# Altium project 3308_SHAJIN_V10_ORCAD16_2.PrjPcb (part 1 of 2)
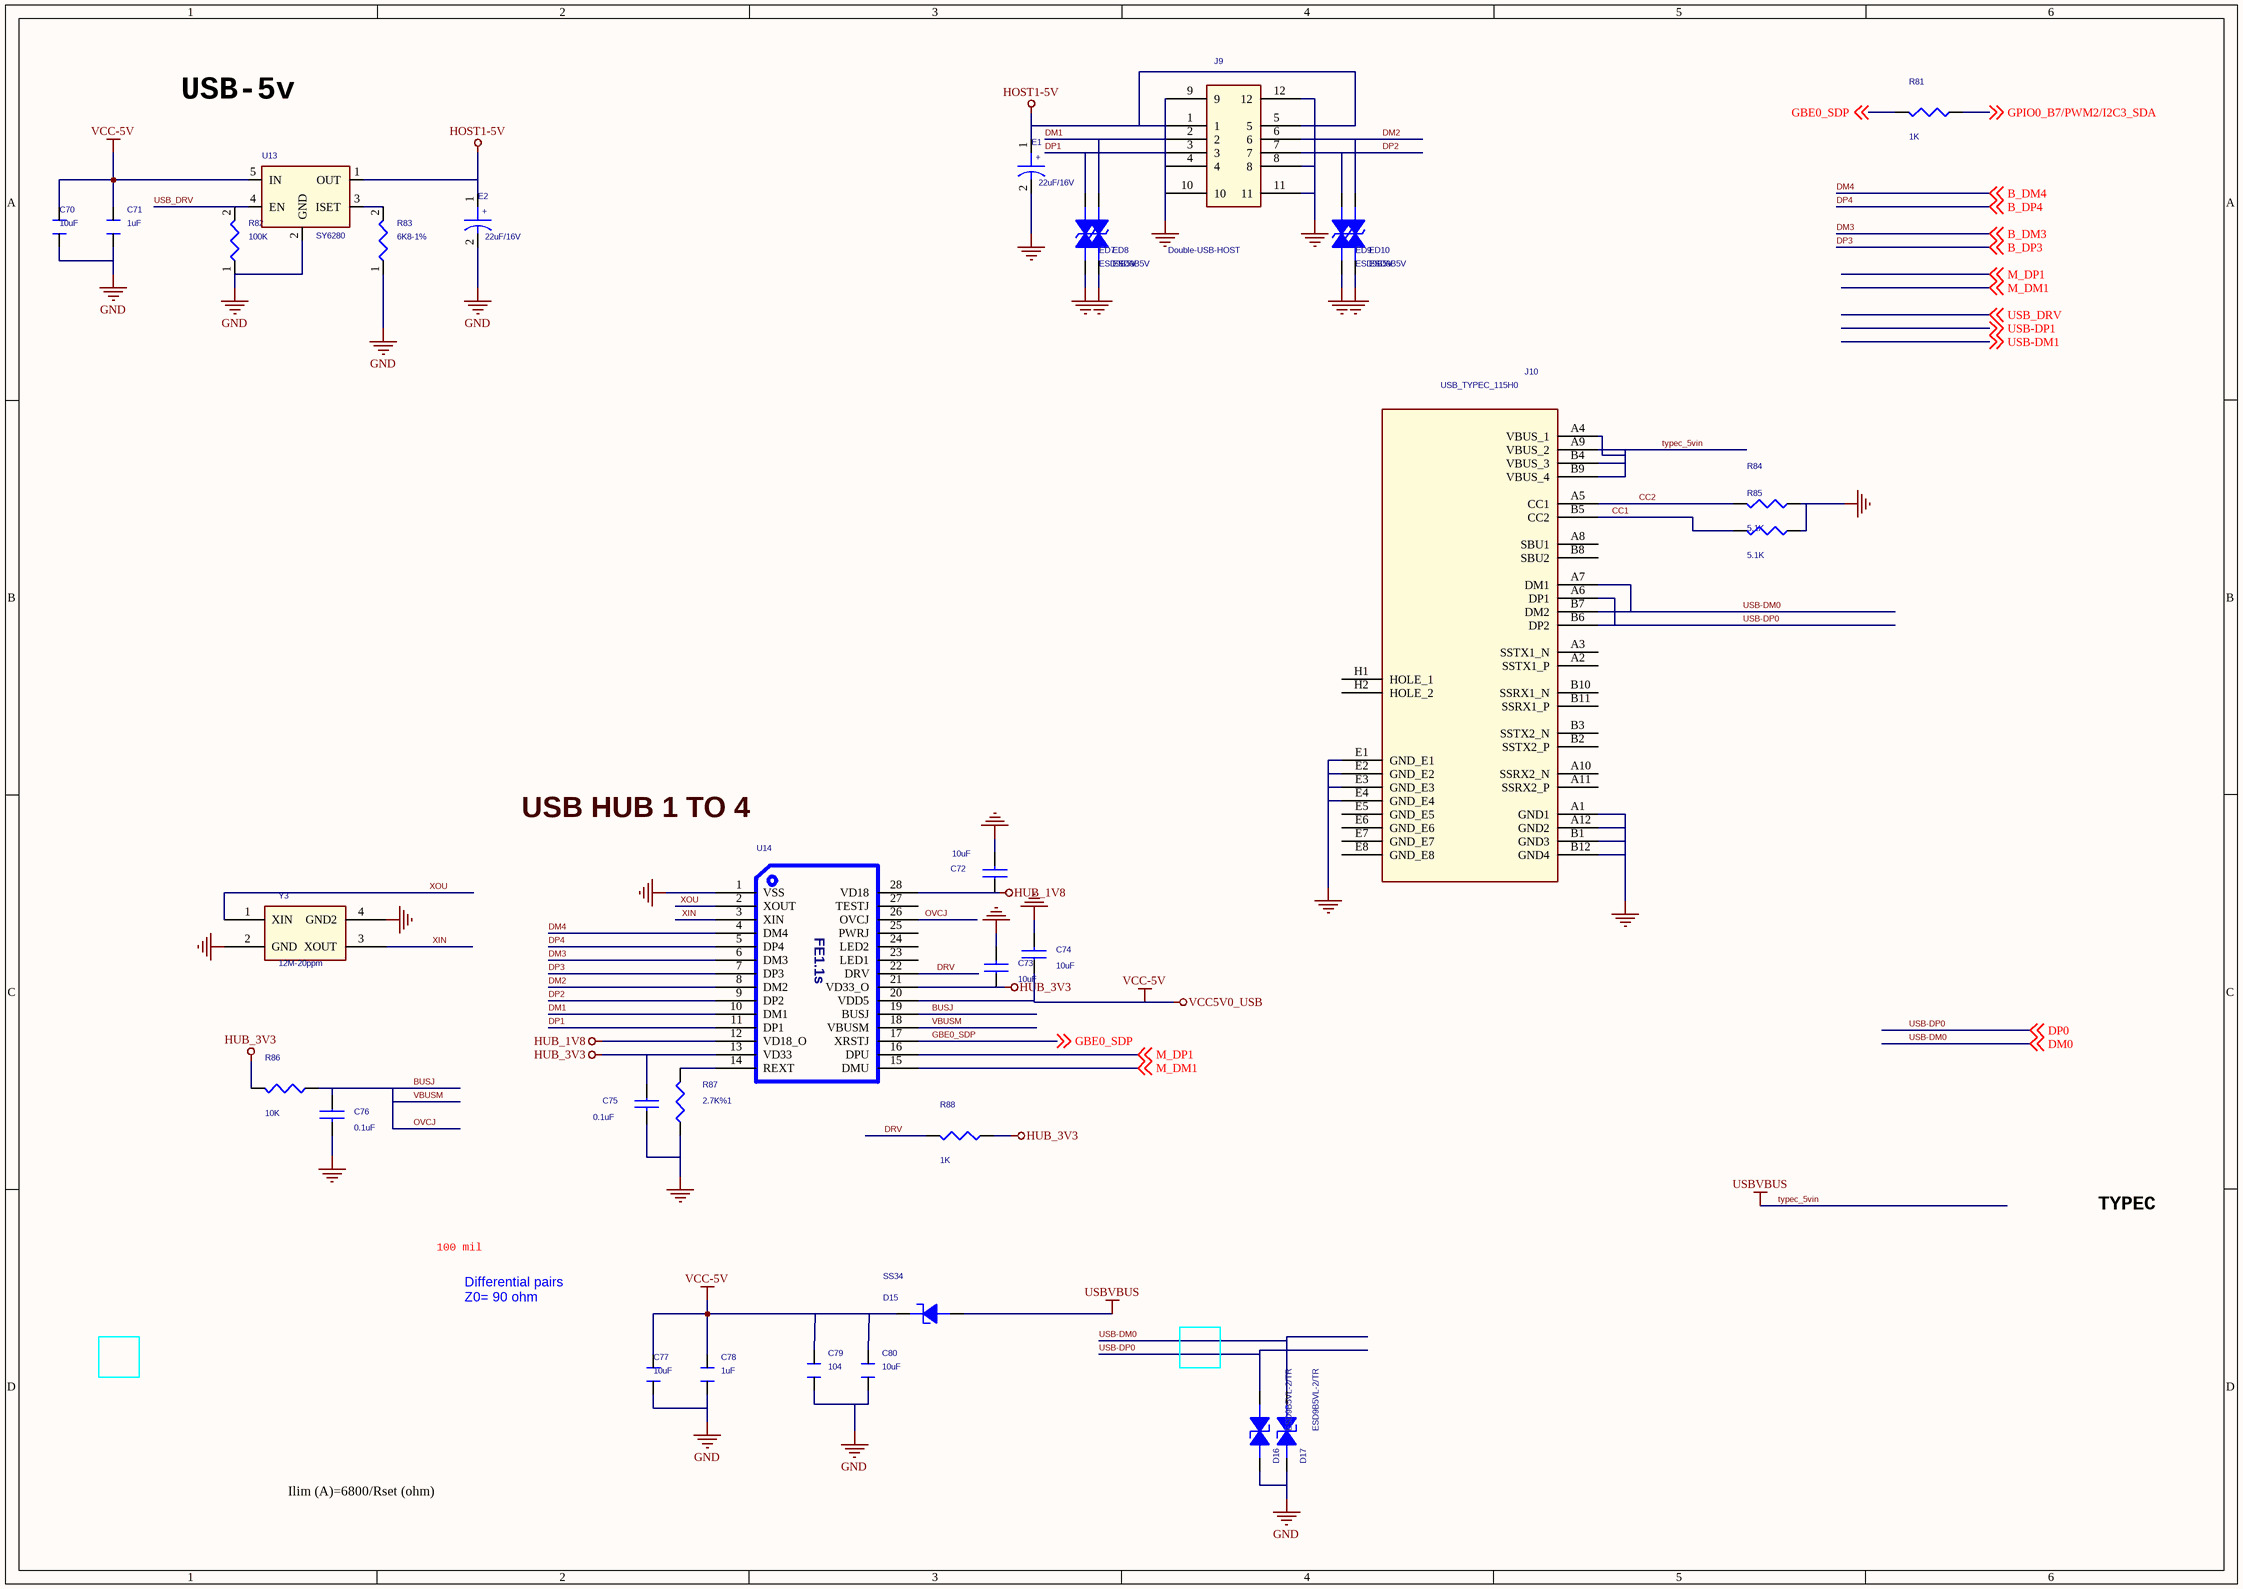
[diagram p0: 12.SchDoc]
11 sheets, 267 parts. Net scope: global (net labels, ports and power ports of the same name join across sheets).
Sheets:
  12.SchDoc
  11.SchDoc
  10.SchDoc
  09.SchDoc
  08.SchDoc
  07.SchDoc
  05.SchDoc
  04.SchDoc
  03.SchDoc
  02.SchDoc
  01.SchDoc

## Sheet 12.SchDoc
size 420 x 297 mm

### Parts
C70  10uF  [C0603]
C71  1uF  [C0402]
C72  10uF  [C0805]
C73  10uF  [C0805]
C74  10uF  [C0805]
C75  0.1uF  [C0402]
C76  0.1uF  [C0402]
C77  10uF  [C0603]
C78  1uF  [C0402]
C79  104  [C0402]
C80  10uF  [C0603]
D15  SS34  [SOD123]
D16  ESD9B5VL-2/TR  [C0402]
D17  ESD9B5VL-2/TR  [C0402]
E1  22uF/16V  [C0805]
E2  22uF/16V  [C0805]
ED7  ESD9B5V  [E0402]
ED8  ESD9B5V  [E0402]
ED9  ESD9B5V  [E0402]
ED10  ESD9B5V  [E0402]
J9  Double-USB-HOST  [USB_DUAL]
J10  USB_TYPEC_115H0  [TYPEC-16PIN-SMD1]
R81  1K  [R0402]
R82  100K  [R0402]
R83  6K8-1%  [R0402]
R84  5.1K  [R0402]
R85  5.1K  [R0402]
R86  10K  [R0402]
R87  2.7K%1  [R0402]
R88  1K  [R0402]
U13  SY6280  [SOT23-6]
U14  FE1_1s_SSOP28  [SSOP28-HUB]  (value not drawn)
Y3  12M-20ppm  [CRY-3225]

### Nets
GND: C70.1 C71.1 C72.2 C73.2 C74.2 C75.2 C76.2 C77.1 C78.1 C79.1 C80.1 D16.2(CATHODE) D17.2(CATHODE) E1.2 E2.2 ED7.2 ED8.2 ED9.2 ED10.2 J9.4 J9.8 J9.9 J9.10 J9.11 J9.12 J10.A1(GND1) J10.A12(GND2) J10.B1(GND3) J10.B12(GND4) J10.E1(GND_E1) J10.E2(GND_E2) J10.E3(GND_E3) J10.E4(GND_E4) R82.1 R83.1 R84.1 R85.1 R87.1 U13.2(GND) U14.1(VSS) Y3.2(GND) Y3.4(GND2)  [project net ABLU0]
HOST1-5V: E1.1 E2.1 J9.1 J9.5 U13.1(OUT)
HUB_1V8: C72.1 U14.12(VD18_O) U14.28(VD18)
HUB_3V3: C73.1 C75.1 R86.2 R88.1 U14.13(VD33) U14.21(VD33_O)
typec_5vin: D15.1(ANODE) J10.A4(VBUS_1) J10.A9(VBUS_2) J10.B4(VBUS_3) J10.B9(VBUS_4)  [also labelled USBVBUS]
VCC-5V: C70.2 C71.2 C74.1 C77.2 C78.2 C79.2 C80.2 D15.2(CATHODE) U13.5(IN) U14.20(VDD5)  [also labelled VCC5V0_USB]  [project net 5V]
B_DM3: U14.6(DM3) ; off-sheet B_DM3  [also labelled DM3]
B_DP3: U14.7(DP3) ; off-sheet B_DP3  [also labelled DP3]
BUSJ: C76.1 R86.1 U14.18(VBUSM) U14.19(BUSJ) U14.26(OVCJ)  [also labelled OVCJ, VBUSM]
CC1: J10.B5(CC2) R85.2
CC2: J10.A5(CC1) R84.2
DM1: ED8.1 J9.2 U14.10(DM1)
DM2: ED10.1 J9.6 U14.8(DM2)
DM4: U14.4(DM4) ; off-sheet B_DM4  [also labelled B_DM4]
DP1: ED7.1 J9.3 U14.11(DP1)
DP2: ED9.1 J9.7 U14.9(DP2)
DP4: U14.5(DP4) ; off-sheet B_DP4  [also labelled B_DP4]
DRV: R88.2 U14.22(DRV)
GBE0_SDP: R81.2 U14.17(XRSTJ) ; off-sheet GBE0_SDP
GPIO0_B7/PWM2/I2C3_SDA: R81.1 ; off-sheet GPIO0_B7/PWM2/I2C3_SDA
M_DM1: U14.15(DMU) ; off-sheet M_DM1
M_DP1: U14.16(DPU) ; off-sheet M_DP1
USB-DM0: D17.1(ANODE) J10.A7(DM1) J10.B7(DM2) ; off-sheet DM0  [also labelled DM0]
USB-DP0: D16.1(ANODE) J10.A6(DP1) J10.B6(DP2) ; off-sheet DP0  [also labelled DP0]
USB_DRV: R82.2 U13.4(EN) ; off-sheet USB_DRV
XIN: U14.3(XIN) Y3.3(XOUT)
XOU: U14.2(XOUT) Y3.1(XIN)
NetR83_2: R83.2 U13.3(ISET)
NetR87_2: R87.2 U14.14(REXT)

Not connected (* = marked no-connect by the designer): J10 A2(SSTX1_P) A3(SSTX1_N) A8(SBU1) A10(SSRX2_N) A11(SSRX2_P) B2(SSTX2_P) B3(SSTX2_N) B8(SBU2) B10(SSRX1_N) B11(SSRX1_P) E5(GND_E5) E6(GND_E6) E7(GND_E7) E8(GND_E8) H1(HOLE_1) H2(HOLE_2); U14 23(LED1) 24(LED2) 25(PWRJ) 27(TESTJ)

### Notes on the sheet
- USB-5v
- USB HUB 1 TO 4
- 100 mil
- Differential pairs
  Z0= 90 ohm
- TYPEC
- Ilim (A)=6800/Rset (ohm)

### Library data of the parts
C70 C71 C77-C80 = CAPACITOR: ROOM: HDMIUSB
C72-C74 = CAP NP: CAP,MLCC,10uF,+/-10%,X5R,6.3V,SMD0805
C75 C76 = CAP NP: CAP,MLCC,8pF,+/-0.5pF,NPO,6.3V,SMD0402
D15 = DIODE ZENER
D16 D17 = 1_1.5KE100A: 1ST PART DESCRIPTION: WILL ESD9B5V Bidirection ESD Protection; ROOM: HDMIUSB
E1 E2 = CAPACITOR POL_0
ED7-ED10 = DIODE_TVS: ESD Component,5V,0.5P,SMD,0402
J9 = CON4_1
J10 = USB31_TYPE_C: USB Type-C 连接座; Manufacturer: 泰科; Priority: A
R81 R86-R88 = RESISTOR
R82 R83 = R_1: ROOM: HDMIUSB
R84 R85 = R
U13 = RT9266PE_2: ROOM: HDMIUSB
Y3 = CRYSTAL-4_3: Crystal,24.000MHz,+/-30ppm,12pF,SMD3225,-10°C ~ +60   °C

## Sheet 11.SchDoc
size 297 x 209 mm
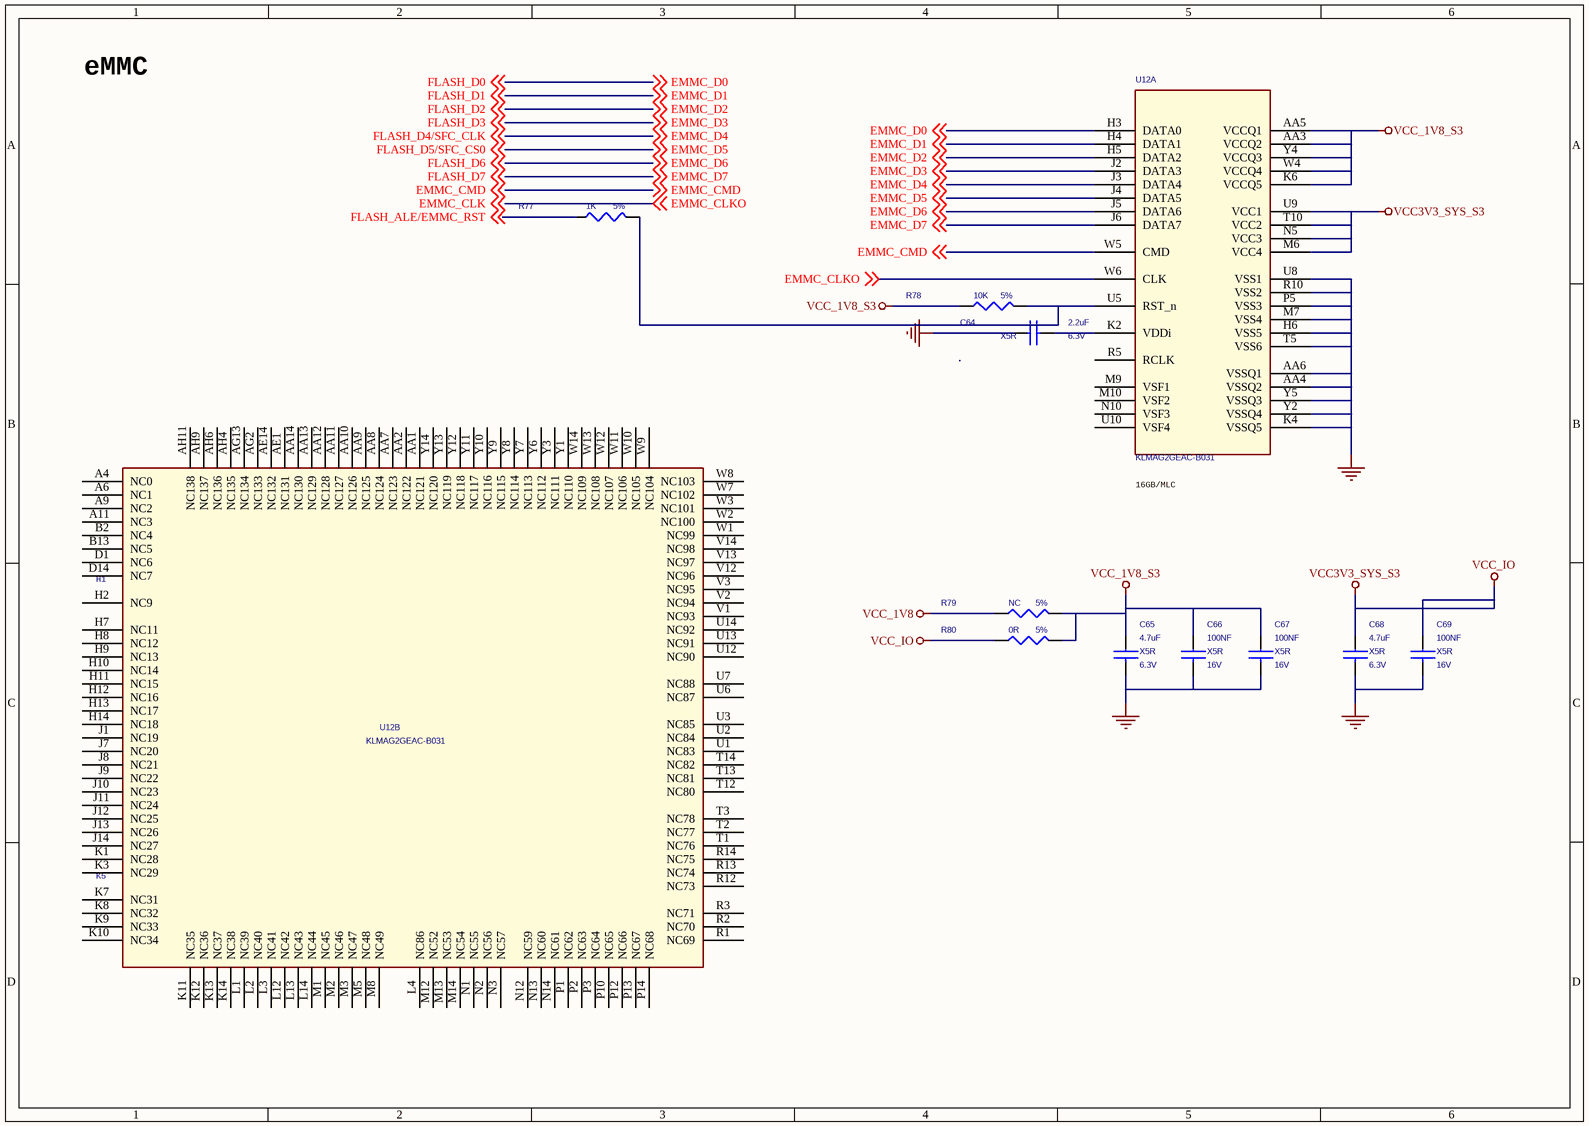
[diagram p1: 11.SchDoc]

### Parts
C64  2.2uF  Dielectric: X5R  Voltage: 6.3V  [C0402]
C65  4.7uF  Dielectric: X5R  Voltage: 6.3V  [C0402]
C66  100NF  Dielectric: X5R  Voltage: 16V  [C0201]
C67  100NF  Voltage: 16V  Dielectric: X5R  [C0201]
C68  4.7uF  Voltage: 6.3V  Dielectric: X5R  [C0402]
C69  100NF  Dielectric: X5R  Voltage: 16V  [C0201]
R77  1K  Tolerance: 5%  [R0402]
R78  10K  Tolerance: 5%  [R0402]
R79  NC  Tolerance: 5%  [R0402]
R80  0R  Tolerance: 5%  [R0402]
U12  KLMAG2GEAC-B031  [INAND_169]  (parts A,B of 2)

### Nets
GND: C64.1 C65.2 C66.2 C67.2 C68.2 C69.2 U12.AA4(VSSQ2) U12.AA6(VSSQ1) U12.H6(VSS5) U12.K4(VSSQ5) U12.M7(VSS4) U12.P5(VSS3) U12.R10(VSS2) U12.T5(VSS6) U12.U8(VSS1) U12.Y2(VSSQ4) U12.Y5(VSSQ3)  [project net ABLU0]
VCC3V3_SYS_S3: C68.1 C69.1 R80.1 U12.M6(VCC4) U12.N5(VCC3) U12.T10(VCC2) U12.U9(VCC1)  [also labelled VCC_IO]  [project net VCC3V3_SYS]
VCC_1V8: R79.1
VCC_1V8_S3: C65.1 C66.1 C67.1 R78.1 R79.2 R80.2 U12.AA3(VCCQ2) U12.AA5(VCCQ1) U12.K6(VCCQ5) U12.W4(VCCQ4) U12.Y4(VCCQ3)
EMMC_CLK: U12.W6(CLK) ; off-sheet EMMC_CLKO, off-sheet EMMC_CLK  [also labelled EMMC_CLKO]
EMMC_CMD: U12.W5(CMD) ; off-sheet EMMC_CMD
EMMC_D0: U12.H3(DATA0) ; off-sheet EMMC_D0, off-sheet FLASH_D0  [also labelled FLASH_D0]
EMMC_D1: U12.H4(DATA1) ; off-sheet EMMC_D1, off-sheet FLASH_D1  [also labelled FLASH_D1]
EMMC_D2: U12.H5(DATA2) ; off-sheet EMMC_D2, off-sheet FLASH_D2  [also labelled FLASH_D2]
EMMC_D3: U12.J2(DATA3) ; off-sheet EMMC_D3, off-sheet FLASH_D3  [also labelled FLASH_D3]
EMMC_D4: U12.J3(DATA4) ; off-sheet EMMC_D4, off-sheet FLASH_D4/SFC_CLK  [also labelled FLASH_D4/SFC_CLK]
EMMC_D5: U12.J4(DATA5) ; off-sheet EMMC_D5, off-sheet FLASH_D5/SFC_CS0  [also labelled FLASH_D5/SFC_CS0]
EMMC_D6: U12.J5(DATA6) ; off-sheet EMMC_D6, off-sheet FLASH_D6  [also labelled FLASH_D6]
EMMC_D7: U12.J6(DATA7) ; off-sheet EMMC_D7, off-sheet FLASH_D7  [also labelled FLASH_D7]
FLASH_ALE/EMMC_RST: R77.1 ; off-sheet FLASH_ALE/EMMC_RST
NetC64_2: C64.2 U12.K2(VDDi)
NetR77_2: R77.2 R78.2 U12.U5(RST_n)

Not connected (* = marked no-connect by the designer): U12 A4(NC0) A6(NC1) A9(NC2) A11(NC3) AA1(NC121) AA2(NC122) AA7(NC123) AA8(NC124) AA9(NC125) AA10(NC126) AA11(NC127) AA12(NC128) AA13(NC129) AA14(NC130) AE1(NC131) AE14(NC132) AG2(NC133) AG13(NC134) AH4(NC135) AH6(NC136) AH9(NC137) AH11(NC138) B2(NC4) B13(NC5) D1(NC6) D14(NC7) H2(NC9) H7(NC11) H8(NC12) H9(NC13) H10(NC14) H11(NC15) H12(NC16) H13(NC17) H14(NC18) J1(NC19) J7(NC20) J8(NC21) J9(NC22) J10(NC23) J11(NC24) J12(NC25) J13(NC26) J14(NC27) K1(NC28) K3(NC29) K7(NC31) K8(NC32) K9(NC33) K10(NC34) K11(NC35) K12(NC36) K13(NC37) K14(NC38) L1(NC39) L2(NC40) L3(NC41) L4(NC86) L12(NC42) L13(NC43) L14(NC44) M1(NC45) M2(NC46) M3(NC47) M5(NC48) M8(NC49) M9(VSF1) M10(VSF2) M12(NC52) M13(NC53) M14(NC54) N1(NC55) N2(NC56) N3(NC57) N10(VSF3) N12(NC59) N13(NC60) N14(NC61) P1(NC62) P2(NC63) P3(NC64) P10(NC65) P12(NC66) P13(NC67) P14(NC68) R1(NC69) R2(NC70) R3(NC71) R5(RCLK) R12(NC73) R13(NC74) R14(NC75) T1(NC76) T2(NC77) T3(NC78) T12(NC80) T13(NC81) T14(NC82) U1(NC83) U2(NC84) U3(NC85) U6(NC87) U7(NC88) U10(VSF4) U12(NC90) U13(NC91) U14(NC92) V1(NC93) V2(NC94) V3(NC95) V12(NC96) V13(NC97) V14(NC98) W1(NC99) W2(NC100) W3(NC101) W7(NC102) W8(NC103) W9(NC104) W10(NC105) W11(NC106) W12(NC107) W13(NC108) W14(NC109) Y1(NC110) Y3(NC111) Y6(NC112) Y7(NC113) Y8(NC114) Y9(NC115) Y10(NC116) Y11(NC117) Y12(NC118) Y13(NC119) Y14(NC120)

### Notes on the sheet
- eMMC
- 16GB/MLC

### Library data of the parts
C64 = CAP NP: cap,2.20uF,+/-10%,6.3V,X5R,C0402; Manufacturer: TDK; RK PN: C1005X5R0J225K050BC; Priority: A; Tolerance: 10%
C65 = CAP NP: cap,4.70uF,+/-10%,6.3V,X5R,C0402; Manufacturer: TDK; RK PN: C1005X5R0J475K050BC; Priority: A; Tolerance: 10%
C66 C69 = CAP NP: cap,100.00nF,+/-10%,16V,X5R,C0402; Manufacturer: TDK; RK PN: C1005X5R1C104K050BA; Priority: A; Tolerance: 10%
C67 = CAP NP: cap,100.00nF,+/-10%,16V,X5R,C0402; Manufacturer PN: C1005X5R1C104K050BA; Manufacturer: TDK; Tolerance: 10%; Priority: A
C68 = CAP NP: cap,4.70uF,+/-10%,6.3V,X5R,C0402; Manufacturer PN: C1005X5R0J475K050BC; Manufacturer: TDK; Tolerance: 10%; Priority: A
R77 R78 = RESISTOR: 通用厚膜电阻,10K,+/-5%,R0402,1/16W.; Manufacturer PN: RC0402JR-0710KL; Manufacturer: YAGEO; Wattage: 1/16W; Priority: A
R79 R80 = RESISTOR: 通用厚膜电阻,10K,+/-5%,R0402,1/16W.; Manufacturer: YAGEO; RK PN: RC0402JR-0710KL; Priority: A; Wattage: 1/16W
U12 = INAND_EMMC_169_2L: 64Gb MLCx2,16GB,EMMC5.0,19nm,5.0,11.5 x 13,更好的满足工艺需求，Fanout方式部分走线跨接再球位上，挖除H1\K5球位; Manufacturer: Samsung（三星）; Priority: A

## Sheet 10.SchDoc
size 420 x 297 mm
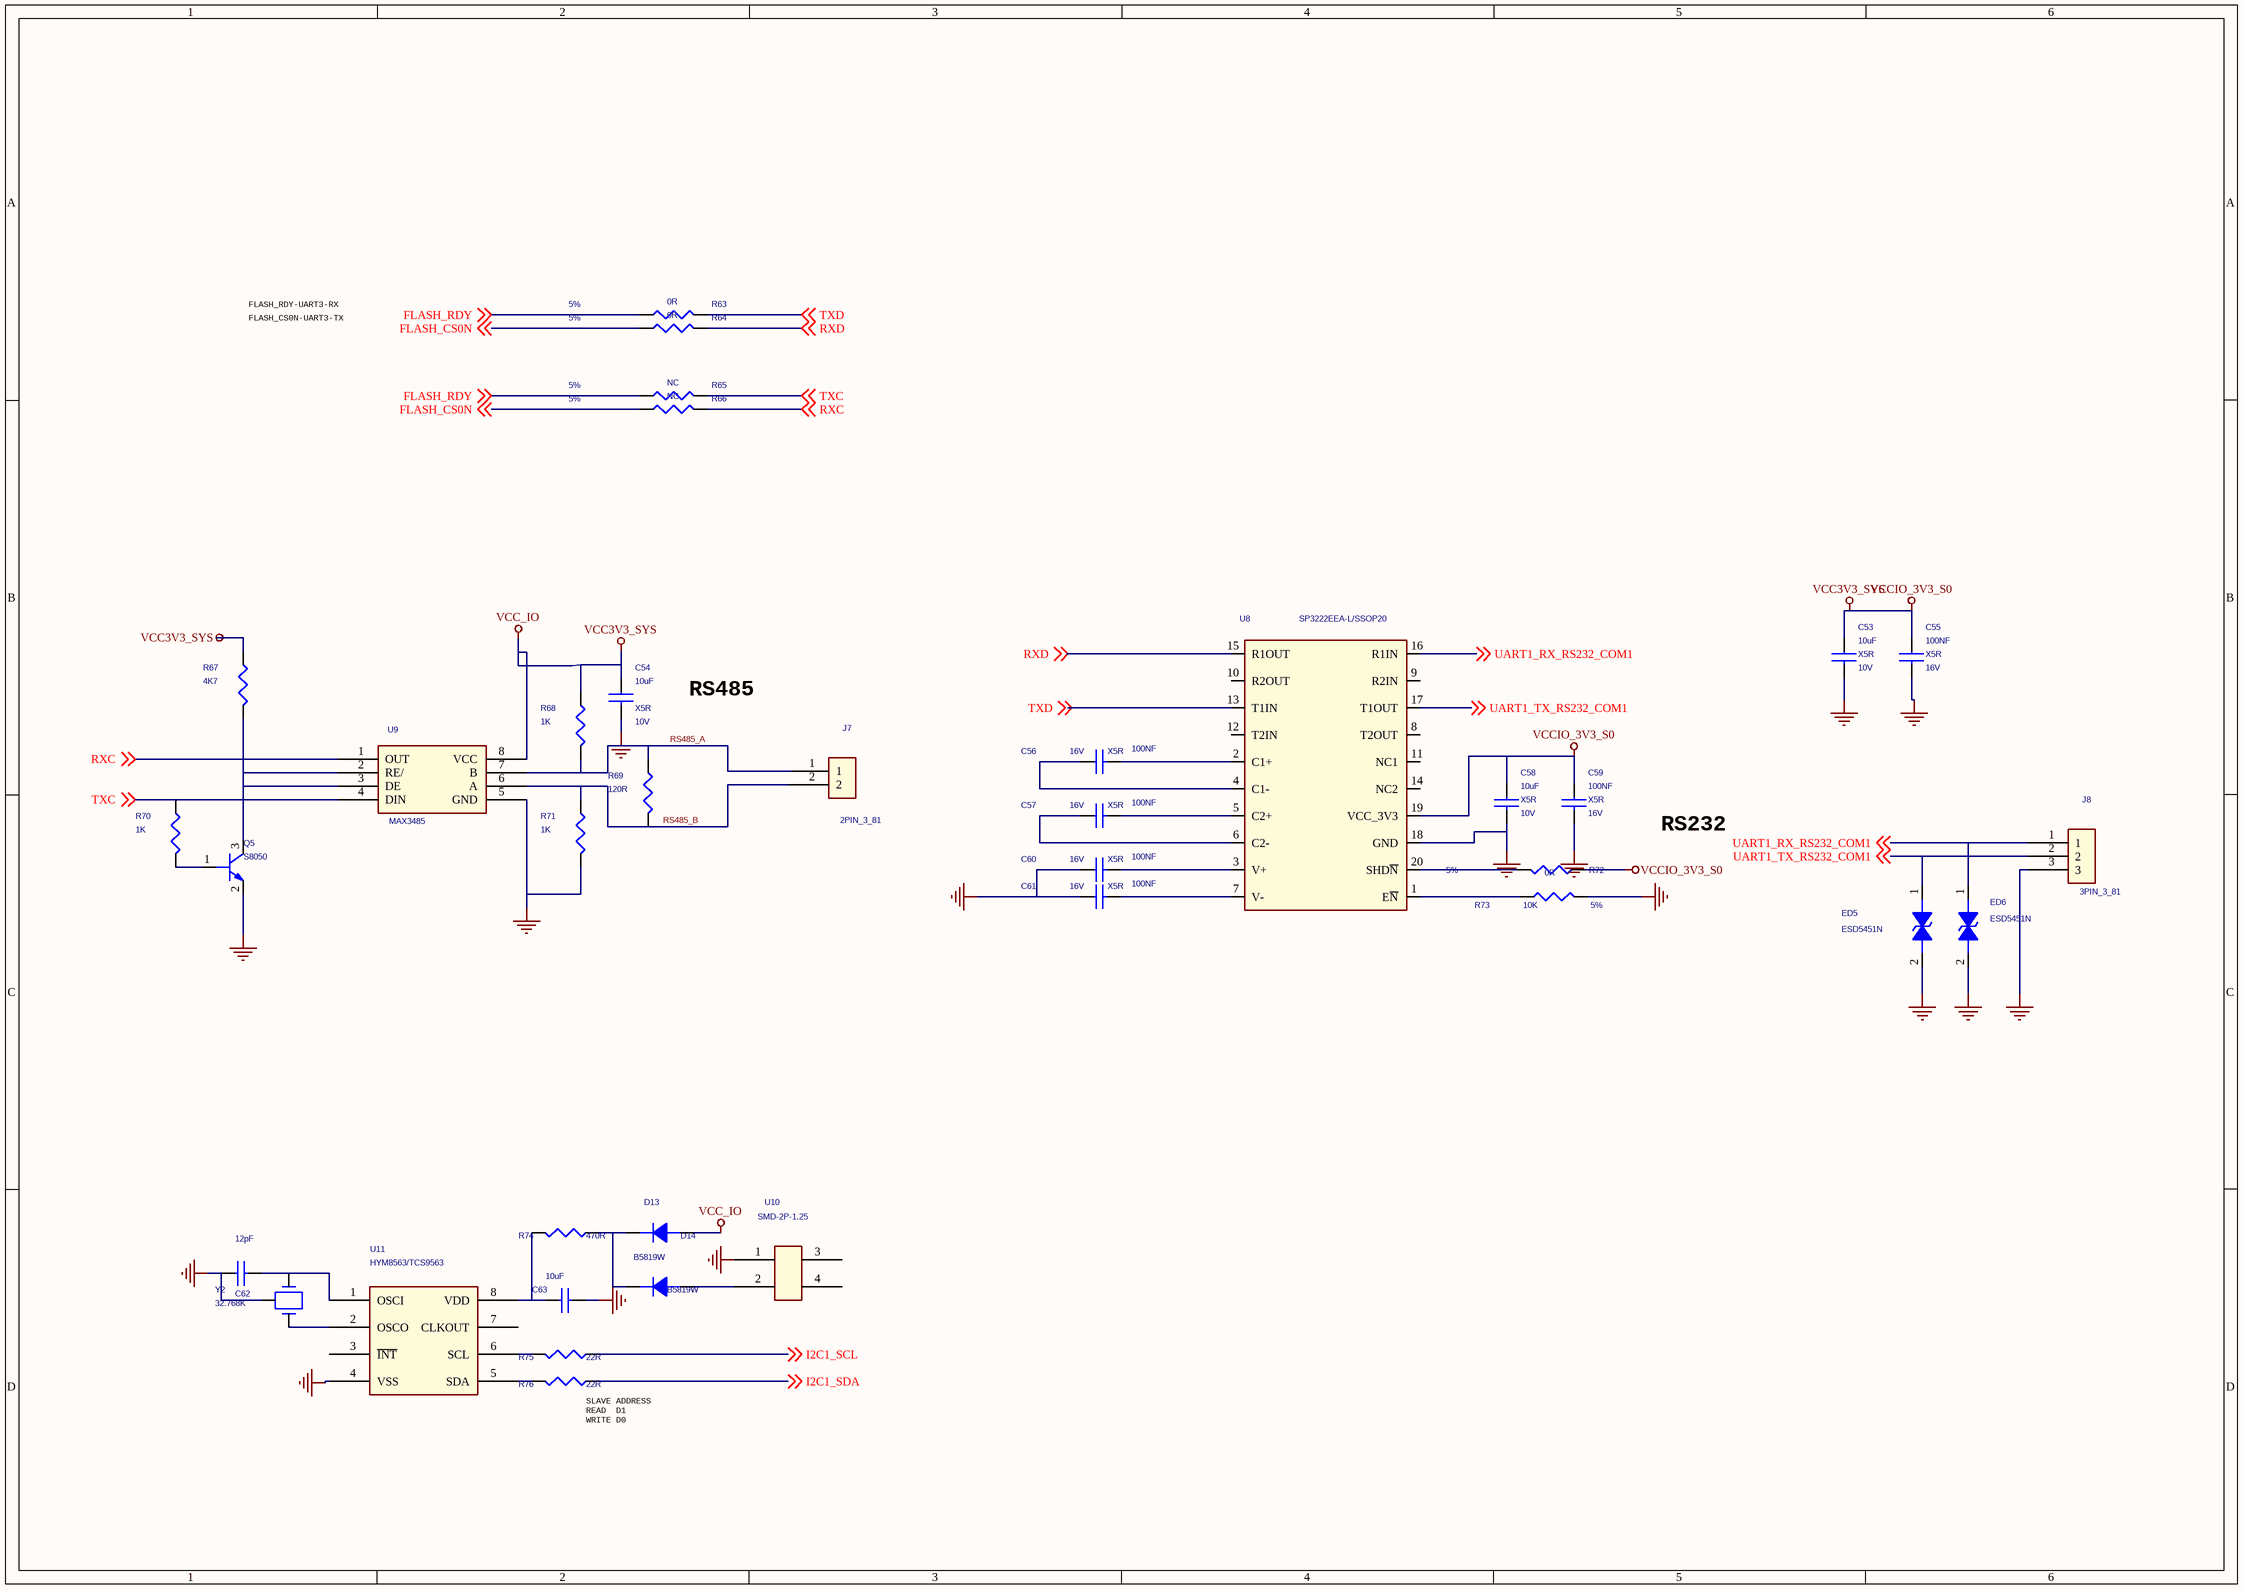
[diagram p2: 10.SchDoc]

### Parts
C53  10uF  Voltage: 10V  Dielectric: X5R  [C0603]
C54  10uF  Voltage: 10V  Dielectric: X5R  [C0603]
C55  100NF  Voltage: 16V  Dielectric: X5R  [C0402]
C56  100NF  Voltage: 16V  Dielectric: X5R  [C0402]
C57  100NF  Voltage: 16V  Dielectric: X5R  [C0402]
C58  10uF  Dielectric: X5R  Voltage: 10V  [C0603]
C59  100NF  Dielectric: X5R  Voltage: 16V  [C0402]
C60  100NF  Voltage: 16V  Dielectric: X5R  [C0402]
C61  100NF  Dielectric: X5R  Voltage: 16V  [C0402]
C62  12pF  [C0402]
C63  10uF  [C0402]
D13  B5819W  [SOD_123]
D14  B5819W  [SOD_123]
ED5  ESD5451N  [ESD0402]
ED6  ESD5451N  [ESD0402]
J7  2PIN_3_81  [2PIN_3_81]
J8  3PIN_3_81  [3PIN_3_81]
Q5  S8050  [SOT23]
R63  0R  Tolerance: 5%  [R0402]
R64  0R  Tolerance: 5%  [R0402]
R65  NC  Tolerance: 5%  [R0402]
R66  NC  Tolerance: 5%  [R0402]
R67  4K7  [R0402]
R68  1K  [R0402]
R69  120R  [R0402]
R70  1K  [R0402]
R71  1K  [R0402]
R72  0R  Tolerance: 5%  [R0402]
R73  10K  Tolerance: 5%  [R0402]
R74  470R  [R0402]
R75  22R  [R0402]
R76  22R  [R0402]
U8  SP3222EEA-L/SSOP20  [SSOP20_1]
U9  MAX3485  [MAX485]
U10  SMD-2P-1.25  [SMD-2P-1.25]
U11  HYM8563/TCS9563  [MSOP8]
Y2  32.768K  [CRY-MC146]

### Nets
GND: C53.2 C54.2 C55.2 C58.2 C59.2 C60.1 C61.1 C62.1 C63.2 ED5.2 ED6.2 J8.3 Q5.2(EMITTER) R71.2 R73.2 U8.18(GND) U9.5(GND) U10.1 U11.4(VSS) Y2.3 Y2.4  [project net ABLU0]
VCC3V3_SYS: C53.1 C54.1 C55.1 C58.1 C59.1 D13.1(A) R67.1 R68.1 R72.1 U8.19(VCC_3V3) U9.8(VCC)  [also labelled VCC_IO, VCCIO_3V3_S0]
FLASH_CS0N: R64.2 R66.2 ; off-sheet FLASH_CS0N
FLASH_RDY: R63.2 R65.2 ; off-sheet FLASH_RDY
I2C1_SCL: R75.2 ; off-sheet I2C1_SCL  [project net I2C0_SCL]
I2C1_SDA: R76.2 ; off-sheet I2C1_SDA  [project net I2C0_SDA]
RS485_A: J7.1 R68.2 R69.1 U9.7(B)
RS485_B: J7.2 R69.2 R71.1 U9.6(A)
RXC: R66.1 U9.1(OUT) ; off-sheet RXC
RXD: R64.1 U8.15(R1OUT) ; off-sheet RXD
TXC: R65.1 R70.1 U9.4(DIN) ; off-sheet TXC
TXD: R63.1 U8.13(T1IN) ; off-sheet TXD
UART1_RX_RS232_COM1: ED6.1 J8.1 U8.16(R1IN) ; off-sheet UART1_RX_RS232_COM1
UART1_TX_RS232_COM1: ED5.1 J8.2 U8.17(T1OUT) ; off-sheet UART1_TX_RS232_COM1
NetC56_1: C56.1 U8.4(C1-)
NetC56_2: C56.2 U8.2(C1+)
NetC57_1: C57.1 U8.6(C2-)
NetC57_2: C57.2 U8.5(C2+)
NetC60_2: C60.2 U8.3(V+)
NetC61_2: C61.2 U8.7(V-)
NetC62_2: C62.2 U11.1(OSCI) Y2.1
NetC63_1: C63.1 R74.1 U11.8(VDD)
NetD13_2: D13.2(K) D14.2(K) R74.2
NetD14_1: D14.1(A) U10.2
NetQ5_1: Q5.1(BASE) R70.2
NetQ5_3: Q5.3(COLLECTOR) R67.2 U9.2(RE/) U9.3(DE)
NetR72_2: R72.2 U8.20(SHD~{N})
NetR73_1: R73.1 U8.1(E~{N})
NetR75_1: R75.1 U11.6(SCL)
NetR76_1: R76.1 U11.5(SDA)
NetU11_2: U11.2(OSCO) Y2.2

Not connected (* = marked no-connect by the designer): U8 8(T2OUT) 9(R2IN) 10(R2OUT) 11(NC1) 12(T2IN) 14(NC2); U10 3 4; U11 3(~{INT}) 7(CLKOUT)

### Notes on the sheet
- FLASH_RDY-UART3-RX
- FLASH_CS0N-UART3-TX
- RS485
- RS232
- (near R76) SLAVE ADDRESS
  READ  D1
  WRITE D0

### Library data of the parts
C53 = CAP NP: cap,4.70uF,+/-10%,10V,X5R,C0603; Manufacturer PN: C1608X5R1A475K080AC; Manufacturer: TDK; Tolerance: 10%; Priority: A
C54 = CAP NP: cap,10.00uF,+/-10%,10V,X5R,C0805; Manufacturer PN: C2012X5R1A106K125AB; Manufacturer: TDK; Tolerance: 10%; Priority: A
C55-C57 C60 = CAP NP: as C67 on sheet 11
C58 = CAP NP: cap,4.70uF,+/-10%,10V,X5R,C0603; Manufacturer: TDK; RK PN: C1608X5R1A475K080AC; Priority: A; Tolerance: 10%
C59 C61 = CAP NP: as C66 on sheet 11
C62 = CAP NP: CAP,MLCC,8pF,+/-0.5pF,NPO,6.3V,SMD0402
C63 = CAP NP: RoHS CHIP CAP 1uF +10/-10% X5R; BOM_VALUE: 1000000; BOM_TYPE: 30
D13 D14 = DIODE: Schottky Barrier，B5819W SOD-123; Manufacturer: 长电; ROOM: CHG; Priority: A
ED5 ED6 = DIODE BI_DIR TRIG: 1-Line, Bi-directional, Transient Voltage Suppressors.17.5pF.; Manufacturer: WillSemi(韦尔半导体); Priority: A
Q5 = NPN: S8050 SOT23; Manufacturer: 长电; Manufacturer PN: S8050_SOT23; Priority: A; Ic: 0.5A; Vceo: 25V; Pc: 0.3W
R63 R64 = RESISTOR: 通用厚膜电阻,22R,+/-5%,R0402,1/16W.; Manufacturer PN: RC0402JR-0722RL; Manufacturer: YAGEO; Wattage: 1/16W; Priority: A
R65 R66 R72 = RESISTOR: 通用厚膜电阻,22R,+/-5%,R0402,1/16W.; Manufacturer: YAGEO; RK PN: RC0402JR-0722RL; Priority: A; Wattage: 1/16W
R67-R71 = RESISTOR
R73 = RESISTOR: as R77 on sheet 11
R74 = RESISTOR: 通用厚膜电阻,5K1,+/-5%,R0402,1/16W.; Manufacturer PN: RC0402JR-075K1L; Manufacturer: YAGEO; Wattage: 1/16W; Tolerance: 5%; Priority: A
R75 R76 = RESISTOR: 通用厚膜电阻,5K1,+/-5%,R0402,1/16W.; Manufacturer: YAGEO; RK PN: RC0402JR-075K1L; Priority: A; Tolerance: 5%; Wattage: 1/16W
U8 = XR21V1410_0
U9 = MAX485
U10 = CON3_6
U11 = LM4990_1: RTC IC,CMOS RTC/Calendar,1.0V~5.5V,TSSOP8,-40 ~85℃; BOM_VALUE: 8; BOM_TYPE: 10
Y2 = CRYSTAL_2: OSC,32.768KHz,+/-25ppm,3.3V,12pF,MC146,-20℃~70℃; BOM_TYPE: 62; BOM_VALUE: 0

## Sheet 09.SchDoc
size 420 x 297 mm
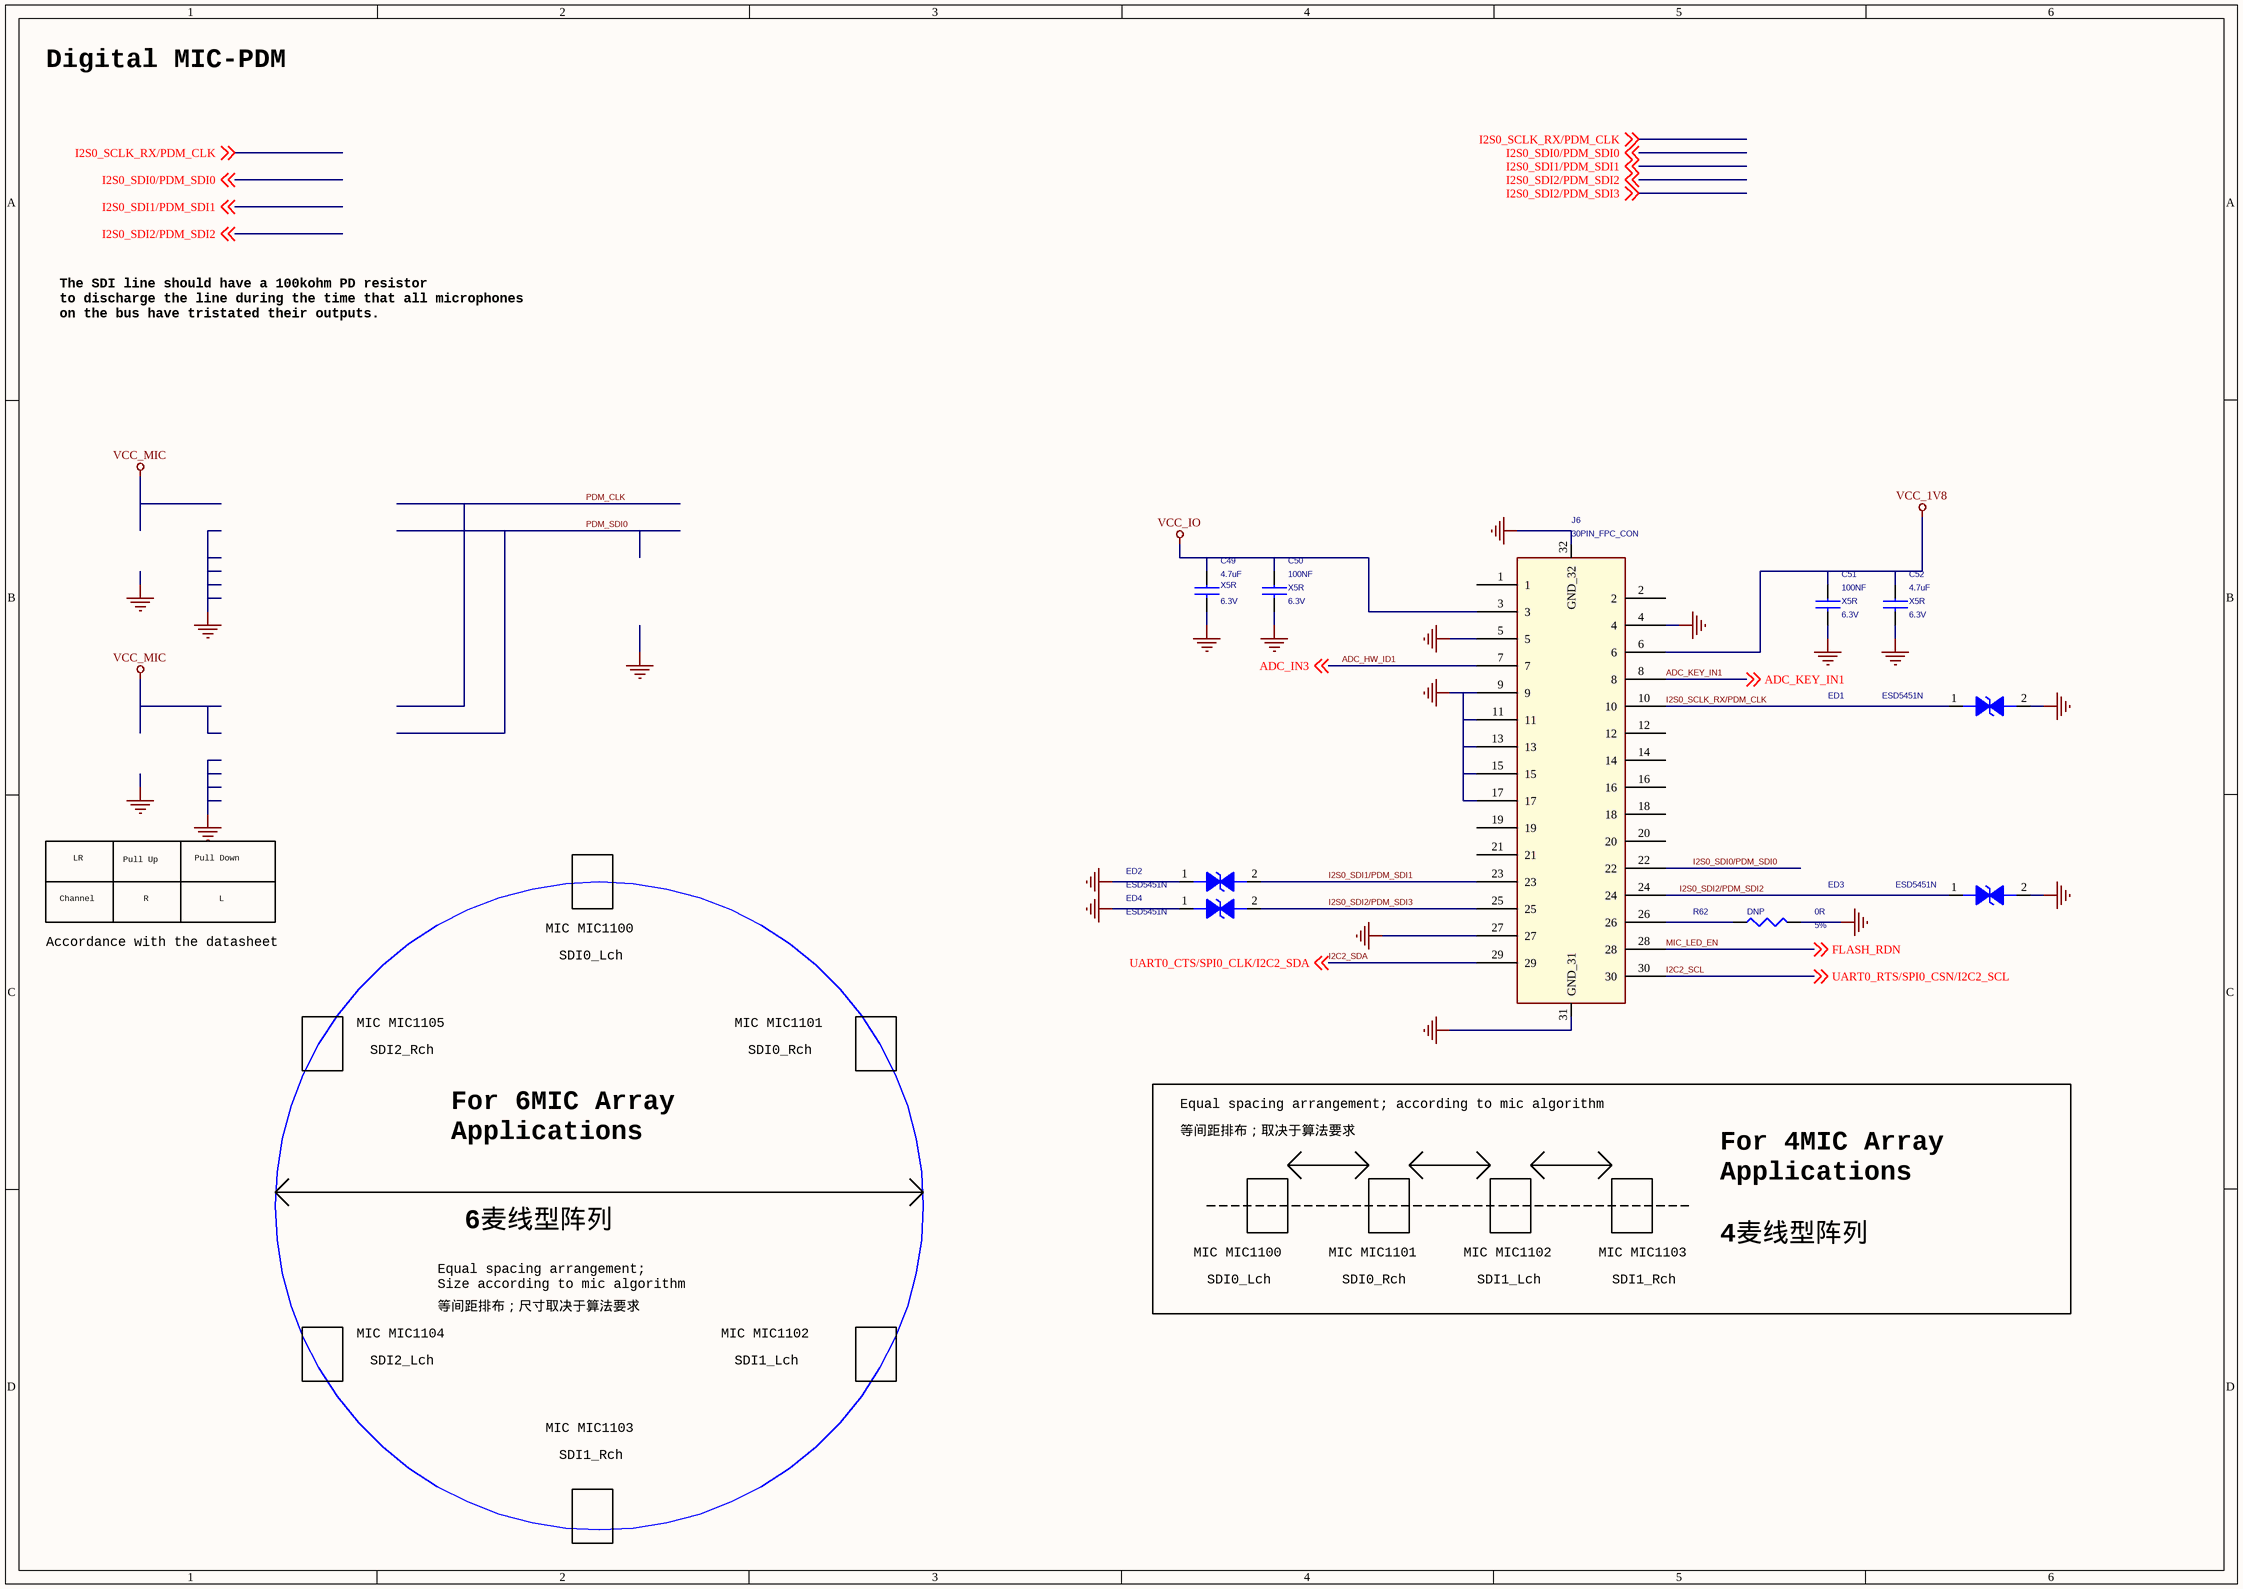
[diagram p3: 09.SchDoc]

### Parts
C49  4.7uF  Dielectric: X5R  Voltage: 6.3V  [C0603]
C50  100NF  Voltage: 6.3V  Dielectric: X5R  [C0402]
C51  100NF  Dielectric: X5R  Voltage: 6.3V  [C0402]
C52  4.7uF  Voltage: 6.3V  Dielectric: X5R  [C0603]
ED1  ESD5451N  [ESD0402]
ED2  ESD5451N  [ESD0402]
ED3  ESD5451N  [ESD0402]
ED4  ESD5451N  [ESD0402]
J6  30PIN_FPC_CON  [FPC30R_0R50_DOWN]
R62  0R  Tolerance: 5%  OPTION: DNP  [R0402]

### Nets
GND: C49.2 C50.2 C51.2 C52.2 ED1.2 ED2.1 ED3.2 ED4.1 J6.4 J6.5 J6.9 J6.11 J6.13 J6.15 J6.17 J6.27 J6.31(GND_31) J6.32(GND_32) R62.2  [project net ABLU0]
VCC_1V8: C51.1 C52.1 J6.6
VCC_IO: C49.1 C50.1 J6.3  [project net VCC3V3_SYS]
ADC_HW_ID1: J6.7 ; off-sheet ADC_IN3  [also labelled ADC_IN3]
ADC_KEY_IN1: J6.8 ; off-sheet ADC_KEY_IN1
I2C2_SCL: J6.30 ; off-sheet UART0_RTS/SPI0_CSN/I2C2_SCL  [also labelled UART0_RTS/SPI0_CSN/I2C2_SCL]
I2C2_SDA: J6.29 ; off-sheet UART0_CTS/SPI0_CLK/I2C2_SDA  [also labelled UART0_CTS/SPI0_CLK/I2C2_SDA]
I2S0_SCLK_RX/PDM_CLK: ED1.1 J6.10 ; off-sheet I2S0_SCLK_RX/PDM_CLK
I2S0_SDI0/PDM_SDI0: J6.22 ; off-sheet I2S0_SDI0/PDM_SDI0
I2S0_SDI1/PDM_SDI1: ED2.2 J6.23 ; off-sheet I2S0_SDI1/PDM_SDI1
I2S0_SDI2/PDM_SDI2: ED3.1 J6.24 ; off-sheet I2S0_SDI2/PDM_SDI2
I2S0_SDI2/PDM_SDI3: ED4.2 J6.25 ; off-sheet I2S0_SDI2/PDM_SDI3
MIC_LED_EN: J6.28 ; off-sheet FLASH_RDN  [also labelled FLASH_RDN]
NetJ6_26: J6.26 R62.1

Not connected (* = marked no-connect by the designer): J6 1 2 12 14 16 18 19 20 21

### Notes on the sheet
- Digital MIC-PDM
- The SDI line should have a 100kohm PD resistor
  to discharge the line during the time that all microphones
  on the bus have tristated their outputs.
- LR
- Pull Up
- Pull Down
- Channel
- R
- L
- MIC MIC1100
- Accordance with the datasheet
- SDI0_Lch
- MIC MIC1105
- SDI2_Rch
- MIC MIC1101
- SDI0_Rch
- For 6MIC Array
  Applications
- 等间距排布；取决于算法要求
- Equal spacing arrangement; according to mic algorithm
- For 4MIC Array
  Applications
- Equal spacing arrangement;
  Size according to mic algorithm
- 6麦线型阵列
- MIC MIC1102
- MIC MIC1103
- 4麦线型阵列
- MIC MIC1104
- 等间距排布；尺寸取决于算法要求
- SDI1_Lch
- SDI1_Rch
- SDI2_Lch

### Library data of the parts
C49 = CAP NP: cap,4.70uF,+/-10%,6.3V,X5R,C0603; Manufacturer: TDK; RK PN: C1608X5R0J475K080AB; Priority: A; Tolerance: 10%
C50 = CAP NP: cap,100.00nF,+/-10%,6.3V,X5R,C0402; Manufacturer PN: C1005X5R0J104K050BA; Manufacturer: TDK; Tolerance: 10%; Priority: A
C51 = CAP NP: cap,100.00nF,+/-10%,6.3V,X5R,C0402; Manufacturer: TDK; RK PN: C1005X5R0J104K050BA; Priority: A; Tolerance: 10%
C52 = CAP NP: cap,4.70uF,+/-10%,6.3V,X5R,C0603; Manufacturer PN: C1608X5R0J475K080AB; Manufacturer: TDK; Tolerance: 10%; Priority: A
ED1-ED4 = DIODE BI_DIR TRIG: as ED5 on sheet 10
J6 = LCD_Hitachi_TX05D99VM1AAA_1
R62 = RESISTOR: 通用厚膜电阻,0R,+/-5%,R0402,1/16W.; Manufacturer: YAGEO; RK PN: RC0402JR-070RL; Priority: A; Wattage: 1/16W

## Sheet 08.SchDoc
size 420 x 297 mm
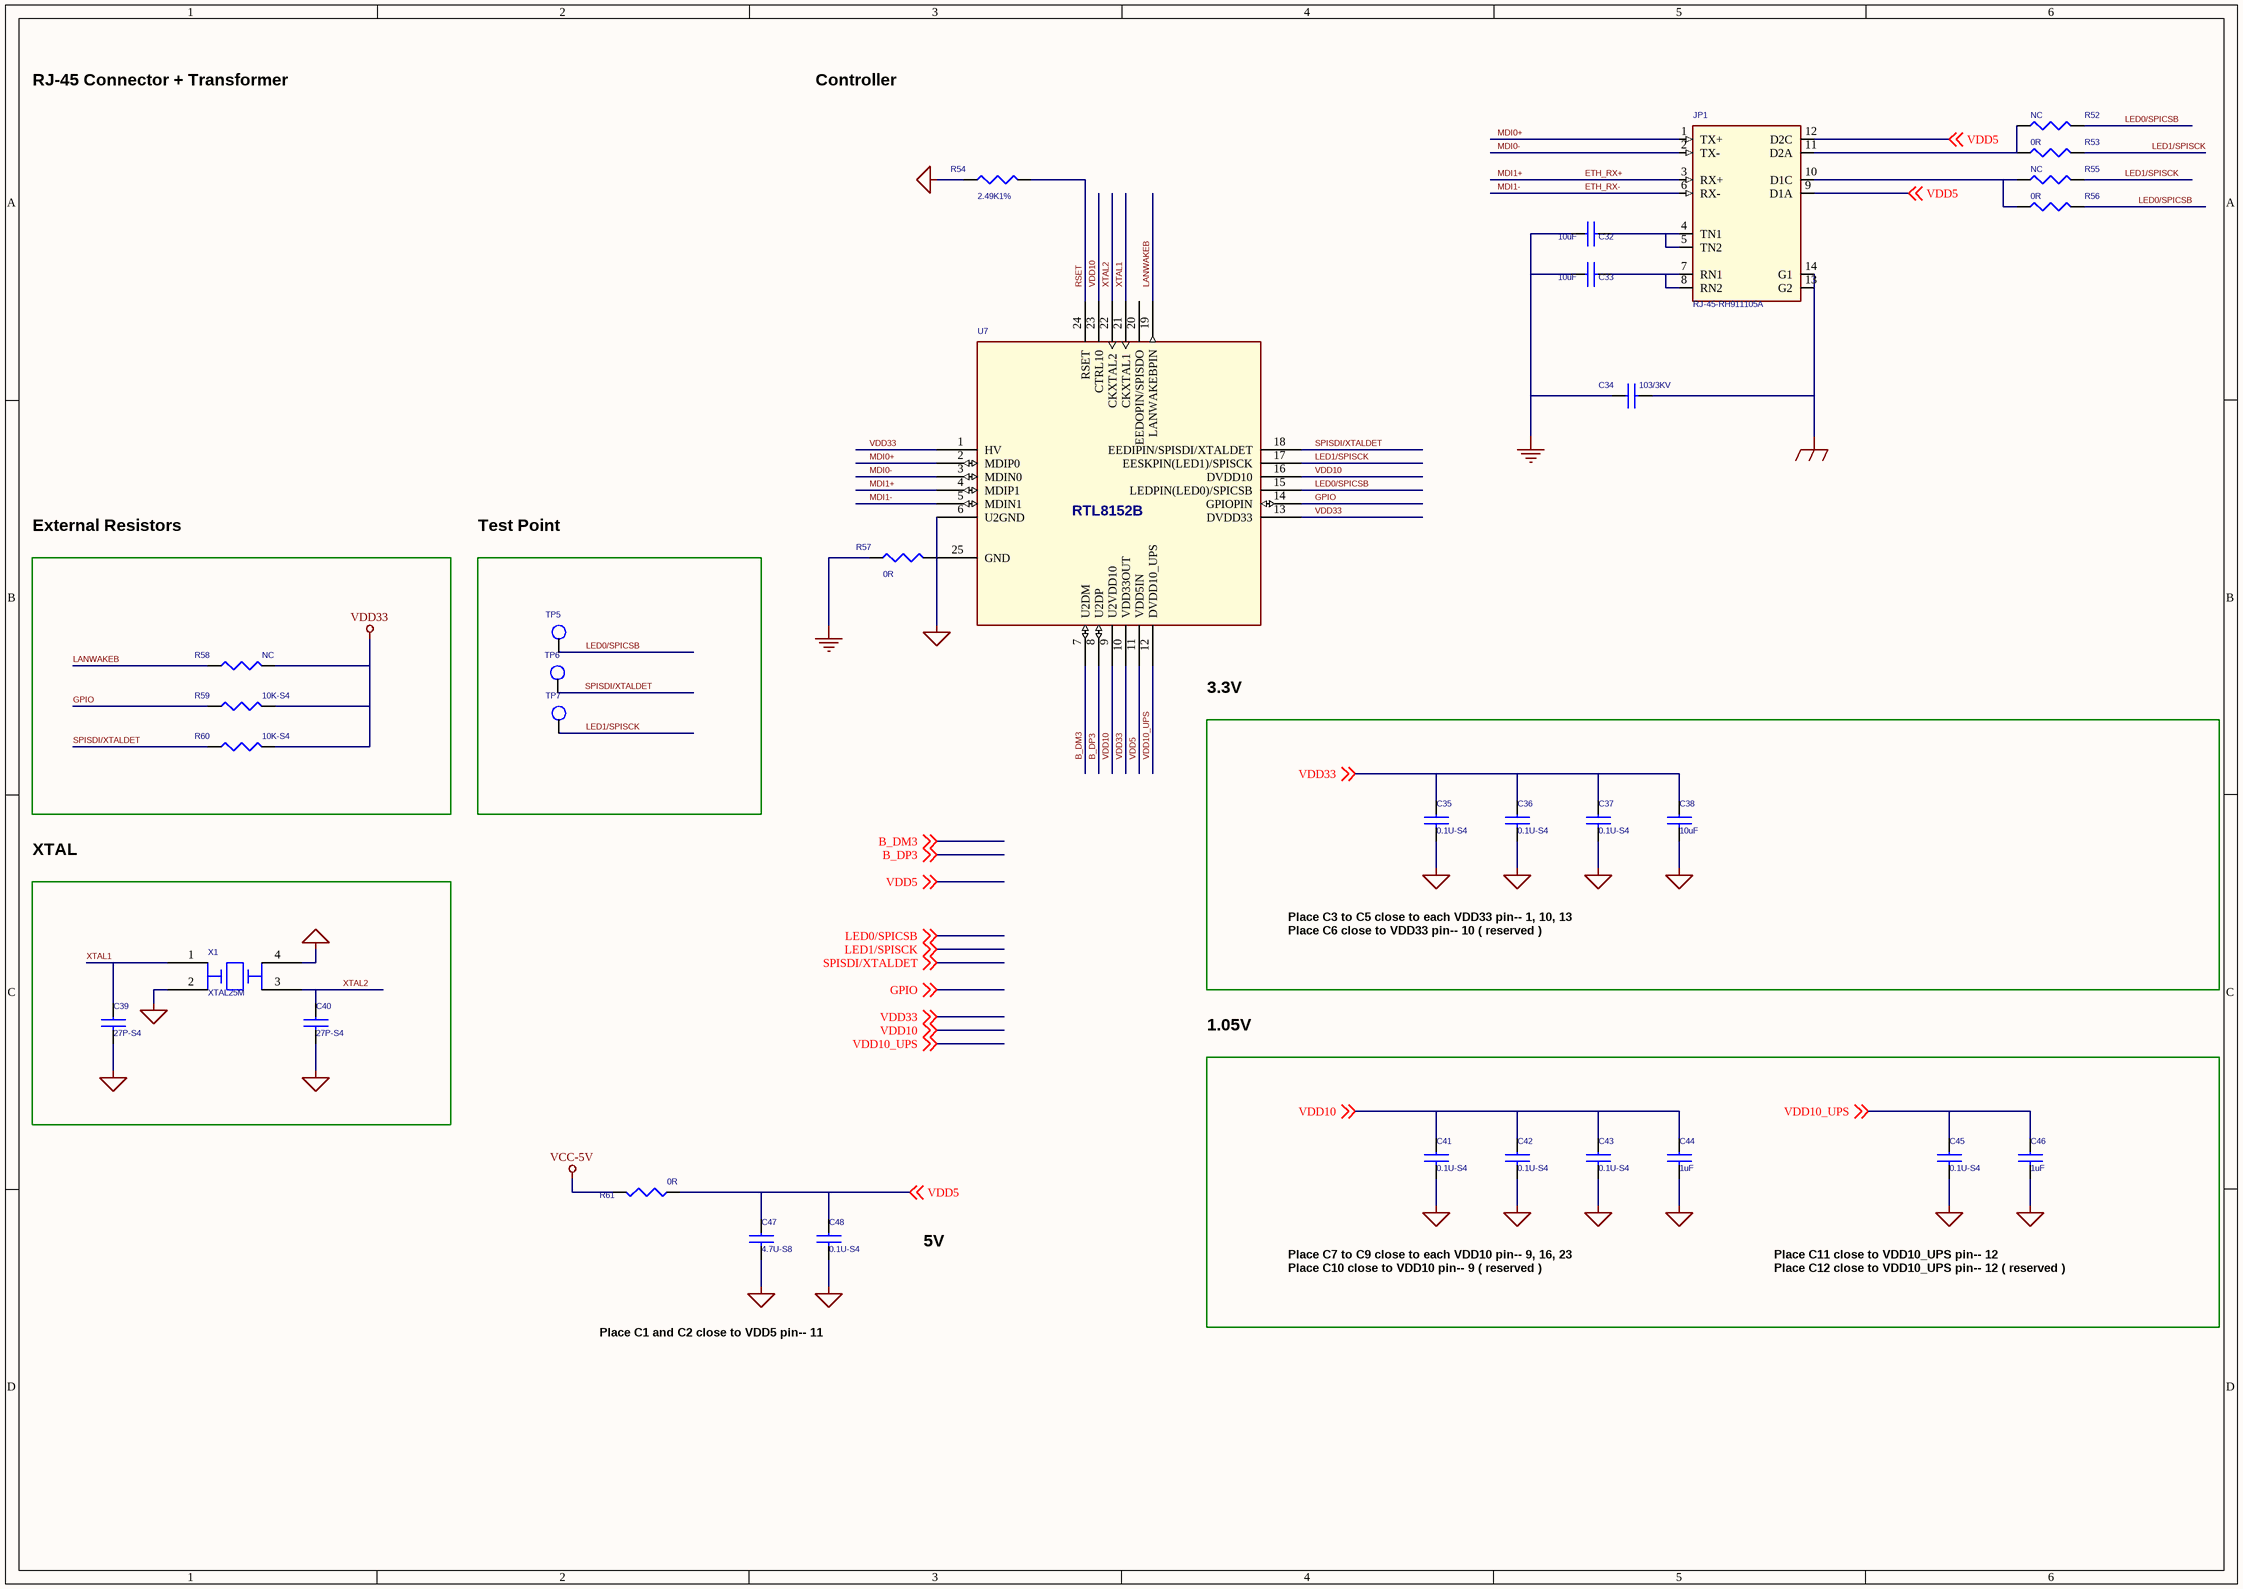
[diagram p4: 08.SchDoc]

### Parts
C32  10uF  [C0805]
C33  10uF  [C0805]
C34  103/3KV  [C1206]
C35  0.1U-S4  [C0402]
C36  0.1U-S4  [C0402]
C37  0.1U-S4  [C0402]
C38  10uF  [C0805]
C39  27P-S4  [C0402]
C40  27P-S4  [C0402]
C41  0.1U-S4  [C0402]
C42  0.1U-S4  [C0402]
C43  0.1U-S4  [C0402]
C44  1uF  [C0402]
C45  0.1U-S4  [C0402]
C46  1uF  [C0603]
C47  4.7U-S8  [C0805]
C48  0.1U-S4  [C0402]
JP1  RJ-45-RH911105A  [RJ45_CON8]
R52  NC  [R0402]
R53  0R  [R0402]
R54  2.49K1%  [R0402]
R55  NC  [R0402]
R56  0R  [R0402]
R57  0R  [R0402]
R58  NC  [R0402]
R59  10K-S4  [R0402]
R60  10K-S4  [R0402]
R61  0R  [R0603]
TP5  TESTPOINT1  [TEST]  (value not drawn)
TP6  TESTPOINT1  [TEST]  (value not drawn)
TP7  TESTPOINT1  [TEST]  (value not drawn)
U7  RTL8152B  [QFN24]
X1  XTAL25M  [cry-d3225]

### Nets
DGND: C35.2 C36.2 C37.2 C38.2 C39.2 C40.2 C41.2 C42.2 C43.2 C44.2 C45.2 C46.2 C47.2 C48.2 R54.1 R57.2 U7.6(U2GND) U7.25(GND) X1.2 X1.4
GND: C32.1 C33.1 C34.1 R57.1  [project net ABLU0]
GND_EARTH: C34.2 JP1.13(G2) JP1.14(G1)
VCC-5V: R61.2  [project net 5V]
VDD33: C35.1 C36.1 C37.1 C38.1 R58.2 R59.2 R60.2 U7.1(HV) U7.10(VDD33OUT) U7.13(DVDD33) ; off-sheet VDD33
B_DM3: U7.7(U2DM) ; off-sheet B_DM3
B_DP3: U7.8(U2DP) ; off-sheet B_DP3
ETH_RX+: JP1.3(RX+) U7.4(MDIP1)  [also labelled MDI1+]
ETH_RX-: JP1.6(RX-) U7.5(MDIN1)  [also labelled MDI1-]
GPIO: R59.1 U7.14(GPIOPIN) ; off-sheet GPIO
LANWAKEB: R58.1 U7.19(LANWAKEBPIN)
LED0/SPICSB: R52.1 R56.1 TP5.1 U7.15(LEDPIN(LED0)/SPICSB) ; off-sheet LED0/SPICSB
LED1/SPISCK: R53.1 R55.1 TP7.1 U7.17(EESKPIN(LED1)/SPISCK) ; off-sheet LED1/SPISCK
MDI0+: JP1.1(TX+) U7.2(MDIP0)
MDI0-: JP1.2(TX-) U7.3(MDIN0)
RSET: R54.2 U7.24(RSET)
SPISDI/XTALDET: R60.1 TP6.1 U7.18(EEDIPIN/SPISDI/XTALDET) ; off-sheet SPISDI/XTALDET
VDD5: C47.1 C48.1 JP1.9(D1A) JP1.12(D2C) R61.1 U7.11(VDD5IN) ; off-sheet VDD5
VDD10: C41.1 C42.1 C43.1 C44.1 U7.9(U2VDD10) U7.16(DVDD10) U7.23(CTRL10) ; off-sheet VDD10
VDD10_UPS: C45.1 C46.1 U7.12(DVDD10_UPS) ; off-sheet VDD10_UPS
XTAL1: C39.1 U7.21(CKXTAL1) X1.1
XTAL2: C40.1 U7.22(CKXTAL2) X1.3
NetC32_2: C32.2 JP1.4(TN1) JP1.5(TN2)
NetC33_2: C33.2 JP1.7(RN1) JP1.8(RN2)
NetJP1_10: JP1.10(D1C) R55.2 R56.2
NetJP1_11: JP1.11(D2A) R52.2 R53.2

Not connected (* = marked no-connect by the designer): U7 20(EEDOPIN/SPISDO)

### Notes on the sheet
- RJ-45 Connector + Transformer
- Controller
- External Resistors
- Test Point
- 3.3V
- XTAL
- Place C3 to C5 close to each VDD33 pin-- 1, 10, 13
  Place C6 close to VDD33 pin-- 10 ( reserved )
- 1.05V
- 5V
- Place C7 to C9 close to each VDD10 pin-- 9, 16, 23
  Place C10 close to VDD10 pin-- 9 ( reserved )
- Place C11 close to VDD10_UPS pin-- 12
  Place C12 close to VDD10_UPS pin-- 12 ( reserved )
- Place C1 and C2 close to VDD5 pin-- 11

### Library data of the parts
C32 C33 = CAP NP: as C66 on sheet 11
C34 = CAP NP_2: 贴片电容
C35-C40 C47 C48 = CAPACITOR NON-POL_0
C41-C46 = CAPACITOR NON-POL_0: ROOM: c_15
JP1 = RJ45_CON8_0
R52 R55 = RESISTOR: 通用厚膜电阻,4K3,+/-5%,R0402,1/16W.; Manufacturer: YAGEO; RK PN: RC0402JR-074K3L; Priority: A; Tolerance: 5%; Wattage: 1/16W
R53 R56 = RESISTOR: 通用厚膜电阻,4K3,+/-5%,R0402,1/16W.; Manufacturer PN: RC0402JR-074K3L; Manufacturer: YAGEO; Wattage: 1/16W; Tolerance: 5%; Priority: A
R54 R57-R61 = R
U7 = RTL8152B_0
X1 = CRYSTAL4/SM_0

## Sheet 07.SchDoc
size 297 x 209 mm
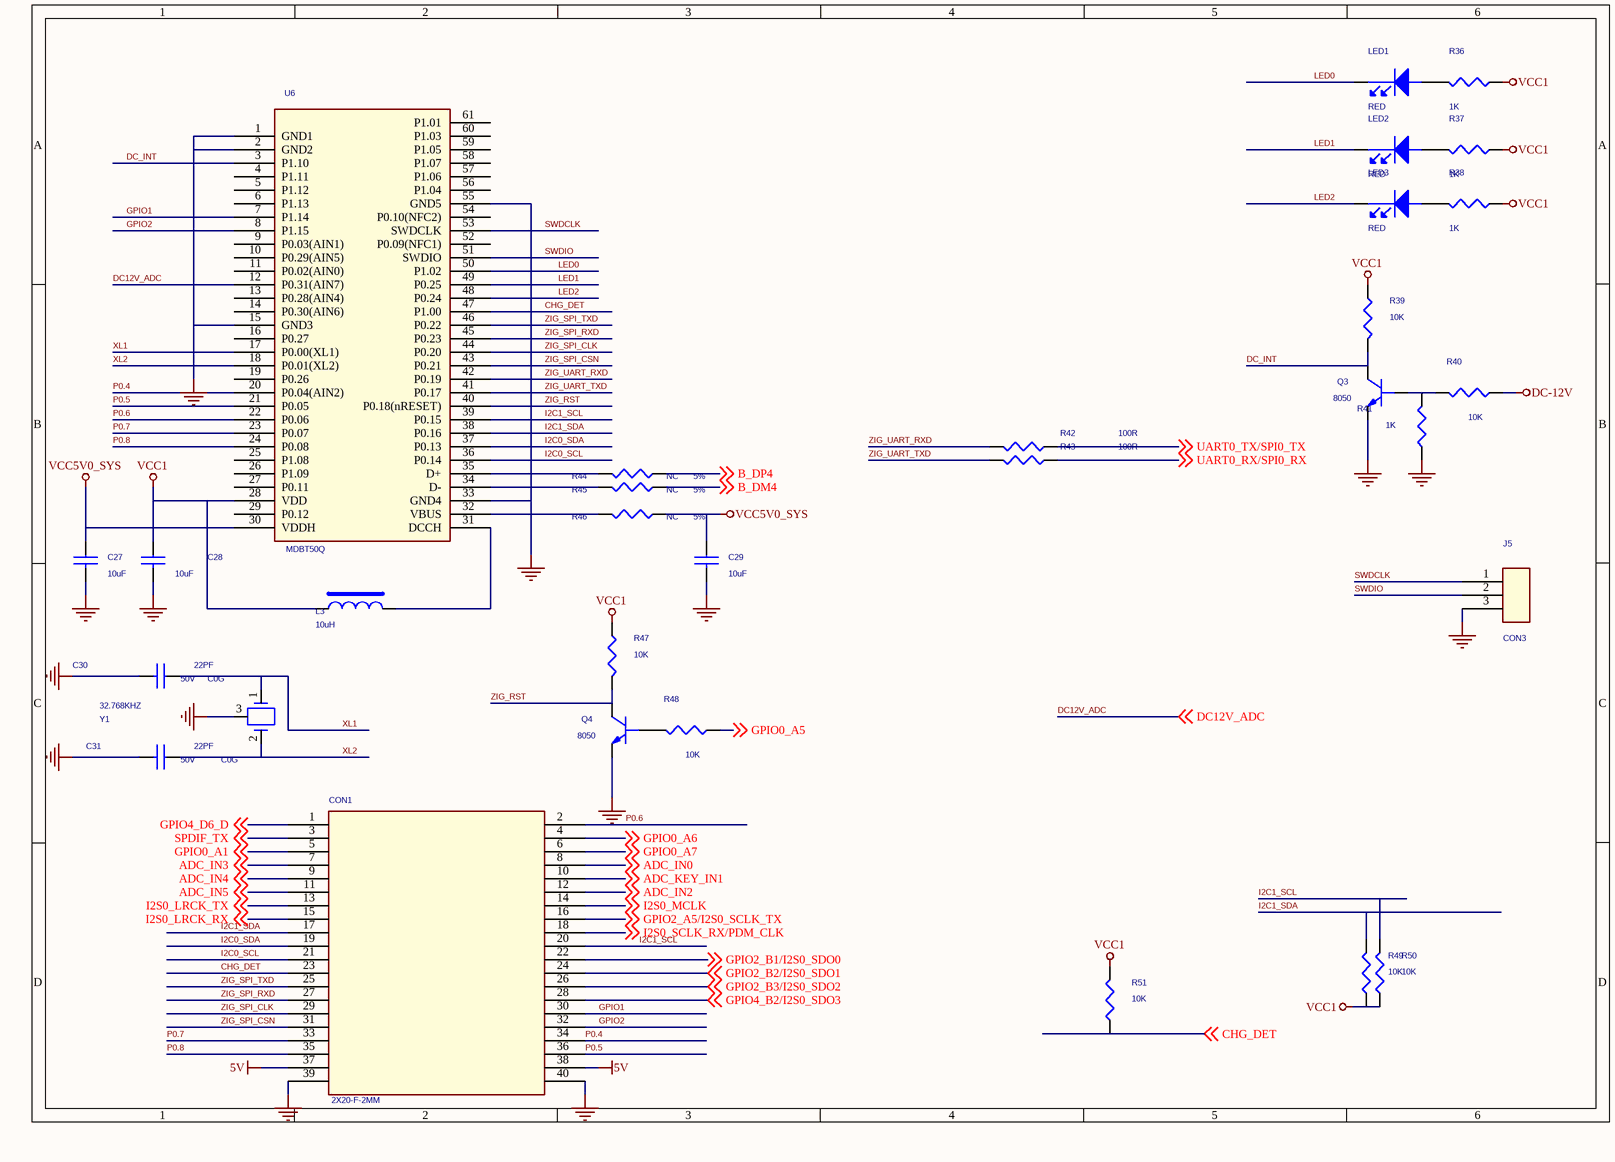
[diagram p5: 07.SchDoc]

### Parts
C27  10uF  [C0805]
C28  10uF  [C0805]
C29  10uF  [C0805]
C30  22PF  Dielectric: C0G  Voltage: 50V  [C0402]
C31  22PF  Dielectric: C0G  Voltage: 50V  [C0402]
CON1  2X20-F-2MM  [DIP40_2X20]
J5  CON3  [CON3X1X1.25-HS]
L3  10uH  [IND-2520]
LED1  RED  [LED0603]
LED2  RED  [LED0603]
LED3  RED  [LED0603]
Q3  8050  [SOT23]
Q4  8050  [SOT23]
R36  1K  [R0402]
R37  1K  [R0402]
R38  1K  [R0402]
R39  10K  [R0402]
R40  10K  [R0402]
R41  1K  [R0402]
R42  100R  [R0402]
R43  100R  [R0402]
R44  NC  Tolerance: 5%  [R0402]
R45  NC  Tolerance: 5%  [R0402]
R46  NC  Tolerance: 5%  [R0402]
R47  10K  [R0402]
R48  10K  [R0402]
R49  10K  [R0402]
R50  10K  [R0402]
R51  10K  [R0402]
U6  MDBT50Q  [MDBT50Q]
Y1  32.768KHZ  [CRY-3215]

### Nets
5V: C27.1 C29.1 CON1.37(+5V) CON1.38(SYS-DCIN) R46.2 U6.30(VDDH)  [also labelled VCC5V0_SYS]
DC-12V: R40.2
GND: C27.2 C28.2 C29.2 C30.2 C31.2 CON1.39(GND) CON1.40(GND) J5.3 Q3.2(E) Q4.2(E) R41.2 U6.1(GND1) U6.2(GND2) U6.15(GND3) U6.33(GND4) U6.55(GND5) Y1.3  [project net ABLU0]
VCC1: C28.1 L3.1 R36.2 R37.2 R38.2 R39.2 R47.2 R49.1 R50.1 R51.2 U6.28(VDD)
ADC_IN0: CON1.8(SPI0-SCLK) ; off-sheet ADC_IN0
ADC_IN2: CON1.12(SPI0-CS) ; off-sheet ADC_IN2
ADC_IN3: CON1.7(UART0-RX) ; off-sheet ADC_IN3  [project net ADC_HW_ID1]
ADC_IN4: CON1.9(UART0-RTS) ; off-sheet ADC_IN4
ADC_IN5: CON1.11(UART1-TX) ; off-sheet ADC_IN5
ADC_KEY_IN1: CON1.10(SPI0-DIN) ; off-sheet ADC_KEY_IN1
B_DM4: R45.2 ; off-sheet B_DM4  [project net DM4]
B_DP4: R44.2 ; off-sheet B_DP4  [project net DP4]
CHG_DET: CON1.23(GPIO-A) R51.1 U6.47(P1.00) ; off-sheet CHG_DET
DC12V_ADC: U6.12(P0.31(AIN7)) ; off-sheet DC12V_ADC
DC_INT: Q3.3(C) R39.1 U6.3(P1.10)
GPIO0_A1: CON1.5(UART0-TX) ; off-sheet GPIO0_A1
GPIO0_A5: R48.2 ; off-sheet GPIO0_A5
GPIO0_A6: CON1.4(PWR-BTN-N) ; off-sheet GPIO0_A6
GPIO0_A7: CON1.6(RST-BTN-N) ; off-sheet GPIO0_A7
GPIO1: CON1.30(GPIO-H) U6.7(P1.14)
GPIO2: CON1.32(GPIO-J) U6.8(P1.15)
GPIO2_A5/I2S0_SCLK_TX: CON1.16(PCM-FS/I2S-WC) ; off-sheet GPIO2_A5/I2S0_SCLK_TX
GPIO2_B1/I2S0_SDO0: CON1.22(PCM-DI/I2S-DI) ; off-sheet GPIO2_B1/I2S0_SDO0
GPIO2_B2/I2S0_SDO1: CON1.24(GPIO-B) ; off-sheet GPIO2_B2/I2S0_SDO1
GPIO2_B3/I2S0_SDO2: CON1.26(GPIO-D) ; off-sheet GPIO2_B3/I2S0_SDO2
GPIO4_B2/I2S0_SDO3: CON1.28(GPIO-F) ; off-sheet GPIO4_B2/I2S0_SDO3
GPIO4_D6_D: CON1.1(GND) ; off-sheet GPIO4_D6_D
I2C0_SCL: CON1.20(PCM-DO/I2S-DO) CON1.21(I2C1-SDA) R50.2 U6.36(P0.14) U6.39(P0.15)  [also labelled I2C1_SCL]
I2C0_SDA: CON1.17(I2C0-SDA) CON1.19(I2C1-SCL) R49.2 U6.37(P0.13) U6.38(P0.16)  [also labelled I2C1_SDA]
I2S0_LRCK_RX: CON1.15(I2C0-SCL) ; off-sheet I2S0_LRCK_RX
I2S0_LRCK_TX: CON1.13(UART1-RX) ; off-sheet I2S0_LRCK_TX
I2S0_MCLK: CON1.14(SPI0-DOUT) ; off-sheet I2S0_MCLK
I2S0_SCLK_RX/PDM_CLK: CON1.18(PCM-CLK/I2S-BC) ; off-sheet I2S0_SCLK_RX/PDM_CLK
LED0: LED1.2(CATHODE) U6.50(P1.02)
LED1: LED2.2(CATHODE) U6.49(P0.25)
LED2: LED3.2(CATHODE) U6.48(P0.24)
P0.4: CON1.34(GPIO-L) U6.20(P0.04(AIN2))
P0.5: CON1.36(SYS-DCIN) U6.21(P0.05)
P0.6: CON1.2(GND) U6.22(P0.06)
P0.7: CON1.33(GPIO-K) U6.23(P0.07)
P0.8: CON1.35(+1V8) U6.24(P0.08)
SPDIF_TX: CON1.3(UART0-CTS) ; off-sheet SPDIF_TX
SWDCLK: J5.1 U6.53(SWDCLK)
SWDIO: J5.2 U6.51(SWDIO)
UART0_RX/SPI0_RX: R43.1 ; off-sheet UART0_RX/SPI0_RX
UART0_TX/SPI0_TX: R42.1 ; off-sheet UART0_TX/SPI0_TX
XL1: C30.1 U6.17(P0.00(XL1)) Y1.1
XL2: C31.1 U6.18(P0.01(XL2)) Y1.2
ZIG_RST: Q4.3(C) R47.1 U6.40(P0.18(nRESET))
ZIG_SPI_CLK: CON1.29(GPIO-G) U6.44(P0.20)
ZIG_SPI_CSN: CON1.31(GPIO-I) U6.43(P0.21)
ZIG_SPI_RXD: CON1.27(GPIO-E) U6.45(P0.23)
ZIG_SPI_TXD: CON1.25(GPIO-C) U6.46(P0.22)
ZIG_UART_RXD: R42.2 U6.42(P0.19)
ZIG_UART_TXD: R43.2 U6.41(P0.17)
NetL3_2: L3.2 U6.31(DCCH)
NetLED1_1: LED1.1(ANODE) R36.1
NetLED2_1: LED2.1(ANODE) R37.1
NetLED3_1: LED3.1(ANODE) R38.1
NetQ3_1: Q3.1(B) R40.1 R41.1
NetQ4_1: Q4.1(B) R48.1
NetR44_1: R44.1 U6.35(D+)
NetR45_1: R45.1 U6.34(D-)
NetR46_1: R46.1 U6.32(VBUS)

Not connected (* = marked no-connect by the designer): U6 4(P1.11) 5(P1.12) 6(P1.13) 9(P0.03(AIN1)) 10(P0.29(AIN5)) 11(P0.02(AIN0)) 13(P0.28(AIN4)) 14(P0.30(AIN6)) 16(P0.27) 19(P0.26) 25(P1.08) 26(P1.09) 27(P0.11) 29(P0.12) 52(P0.09(NFC1)) 54(P0.10(NFC2)) 56(P1.04) 57(P1.06) 58(P1.07) 59(P1.05) 60(P1.03) 61(P1.01)

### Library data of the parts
C27-C29 = CAP NP: CAP,MLCC,10uF,+/-10%,X5R,6.3V,SMD0805
C30 C31 = CAP NP: cap,22.00pF,+/-2%,50V,C0G,C0402; Manufacturer: TDK; RK PN: C1005C0G1H220G050BA; Priority: A; Tolerance: 2%
CON1 = CN_0
L3 = INDUCTORS OF FERRITE: Power Inductor,3.3uH,0.2,IND_303015; Manufacturer PN: SWPA3015S3R3MT; Manufacturer: sunlord; Resonace frequency: 68M; Isat: 1.32A; Irms: 1.36A; Tolerance: 20%; DC Resistor: 0.08ohm; Priority: A
LED1-LED3 = LED_0
Q3 Q4 = 40852_1: Trans NPN,SS8050,25V,1500mA,120~400@Vce=1V,Ic=100mA, SOT-23
R36-R38 = RESISTOR
R39 R40 R48 = RESISTOR: 通用厚膜电阻,75K,+/-1%,R0402,1/16W.; Manufacturer: YAGEO; RK PN: RC0402FR-0775KL; Priority: A; Tolerance: 1%; Wattage: 1/16W
R41-R43 R47 = RESISTOR: 通用厚膜电阻,75K,+/-1%,R0402,1/16W.; Manufacturer PN: RC0402FR-0775KL; Manufacturer: YAGEO; Wattage: 1/16W; Tolerance: 1%; Priority: A
R44-R46 = RESISTOR: 通用厚膜电阻,5K1,+/-5%,R0402,1/16W.; Manufacturer: YAGEO; RK PN: RC0402JR-075K1L; Priority: A; Wattage: 1/16W
R49-R51 = RESISTOR: NC/ROHS CHIP RES 0R 1/16W +/-5%
U6 = MDBT50Q_0
Y1 = CRYSTAL_2P_1G: 无源晶振，32.768KHz，MC-146,±20ppm，12.5pF，Hosonic; Manufacturer PN: ETDE32.768W125BMPF; Manufacturer: Hosonic(鸿星电子); Priority: A

## Sheet 05.SchDoc
size 246 x 182 mm
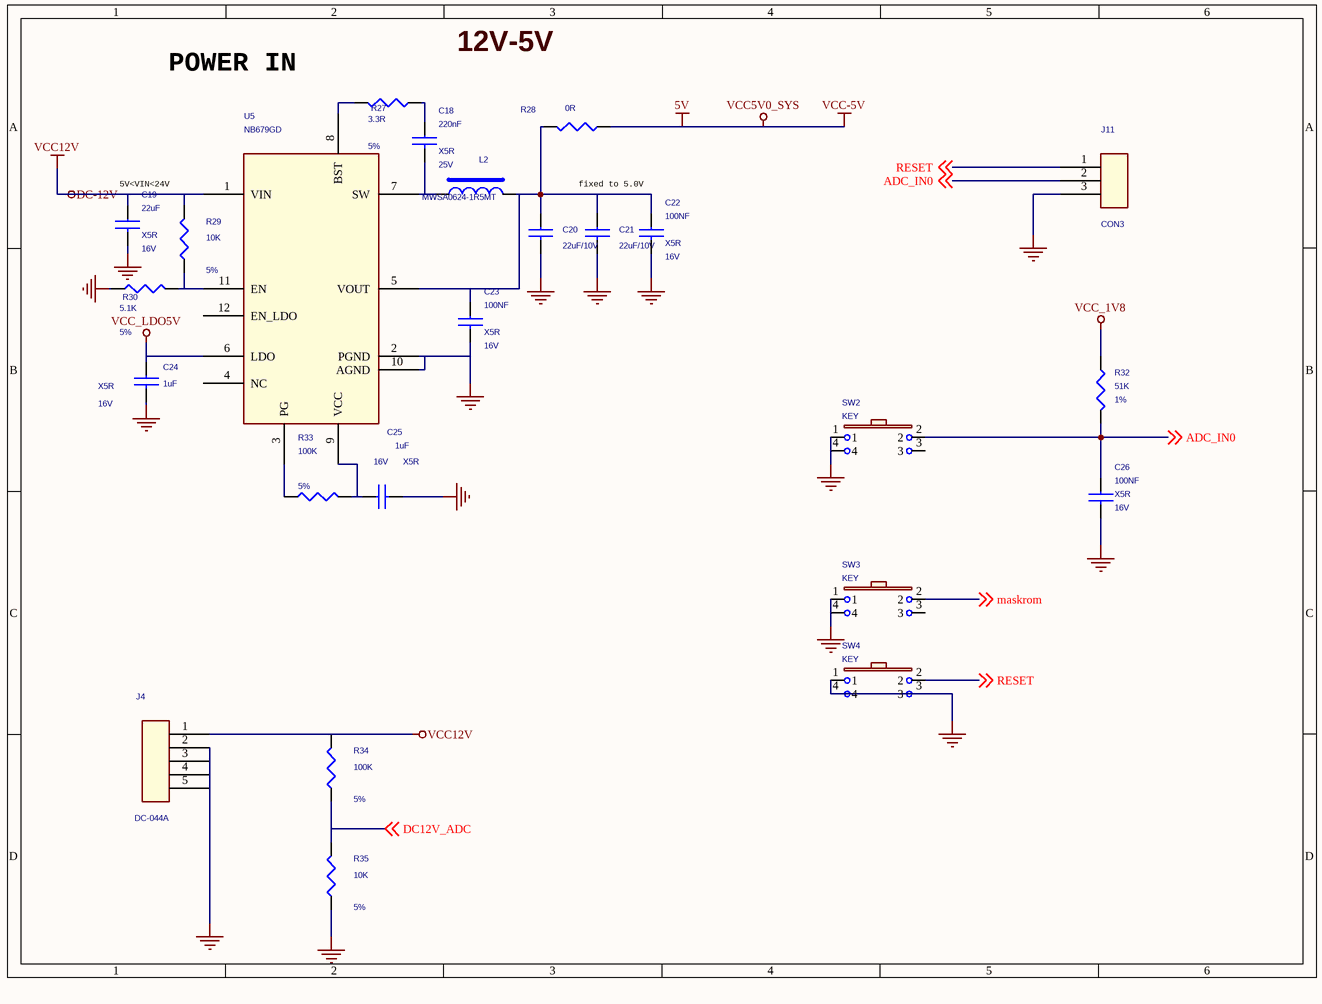
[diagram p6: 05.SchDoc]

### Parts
C18  220nF  Voltage: 25V  Dielectric: X5R  [C0402]
C19  22uF  Dielectric: X5R  Voltage: 16V  [C0805]
C20  22uF/10V  [C0805]
C21  22uF/10V  [C0805]
C22  100NF  Voltage: 16V  Dielectric: X5R  [C0402]
C23  100NF  Dielectric: X5R  Voltage: 16V  [C0402]
C24  1uF  Voltage: 16V  Dielectric: X5R  [C0402]
C25  1uF  Voltage: 16V  Dielectric: X5R  [C0402]
C26  100NF  Dielectric: X5R  Voltage: 16V  [C0402]
J4  DC-044A  [DC-044A]
J11  CON3  [CON3X1X1.25-HS]
L2  MWSA0624-1R5MT  [0624_66X70]
R27  3.3R  Tolerance: 5%  [R0402]
R28  0R  [R1206]
R29  10K  Tolerance: 5%  [R0402]
R30  5.1K  Tolerance: 5%  [R0402]
R32  51K  Tolerance: 1%  [R0402]
R33  100K  Tolerance: 5%  [R0402]
R34  100K  Tolerance: 5%  [R0402]
R35  10K  Tolerance: 5%  [R0402]
SW2  KEY  [YC-6615B]
SW3  KEY  [YC-6615B]
SW4  KEY  [YC-6615B]
U5  NB679GD  [QFN12_3R00X2R00X0R90]

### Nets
5V: R28.1  [also labelled VCC-5V, VCC5V0_SYS]
DC-12V: C19.1 J4.1 R29.2 R34.2 U5.1(VIN)  [also labelled VCC12V]
GND: C19.2 C20.2 C21.2 C22.2 C23.2 C24.2 C25.2 C26.2 J4.2 J4.3 J4.4 J4.5 J11.3 R30.1 R35.1 SW2.1 SW2.4 SW3.1 SW3.4 SW4.1 SW4.3 SW4.4 U5.2(PGND) U5.10(AGND)  [project net ABLU0]
VCC_1V8: R32.1
VCC_LDO5V: C24.1 U5.6(LDO)
ADC_IN0: C26.1 J11.2 R32.2 SW2.2 ; off-sheet ADC_IN0
DC12V_ADC: R34.1 R35.2 ; off-sheet DC12V_ADC
maskrom: SW3.2 ; off-sheet maskrom
RESET: J11.1 SW4.2 ; off-sheet RESET
NetC18_1: C18.1 R27.2
NetC18_2: C18.2 L2.1 U5.7(SW)
NetC20_1: C20.1 C21.1 C22.1 C23.1 L2.2 R28.2 U5.5(VOUT)
NetC25_1: C25.1 R33.1 U5.9(VCC)
NetR27_1: R27.1 U5.8(BST)
NetR29_1: R29.1 R30.2 U5.11(EN)
NetR33_2: R33.2 U5.3(PG)

Not connected (* = marked no-connect by the designer): SW2 3; SW3 3; U5 4(NC) 12(EN_LDO)

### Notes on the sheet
- 12V-5V
- POWER IN
- 5V<VIN<24V
- fixed to 5.0V

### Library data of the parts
C18 = CAP NP: cap,220.00nF,+/-10%,25V,X5R,C0402; Manufacturer PN: C1005X5R1E224K050BC; Manufacturer: TDK; Tolerance: 10%; Priority: A
C19 = CAP NP: cap,10.00uF,+/-10%,16V,X5R,C0805; Manufacturer: TDK; RK PN: C2012X5R1C106K125AC; Priority: A; Tolerance: 10%
C20 C21 = CAP NP: RoHS CHIP CAP 22uF +10/-10% X5R; ROOM: USB+5V; MARK: 106
C22 = CAP NP: as C67 on sheet 11
C23 = CAP NP: as C66 on sheet 11
C24 C25 = CAP NP: cap,1.00uF,+/-10%,16V,X5R,C0402; Manufacturer PN: C1005X5R1C105K050BC; Manufacturer: TDK; Tolerance: 10%; Priority: A
C26 = CAP NP: cap,100.00nF,+/-10%,16V,X5R,C0402; Manufacturer PN: C1005X5R1C104K050BA; Manufacturer: TDK; C_Voltage: 6.3V; Tolerance: 10%; Priority: A; Number: 37
J4 = CON5
L2 = INDUCTORS OF FERRITE
R27 = RESISTOR: 通用厚膜电阻,3R3,+/-5%,R0402,1/16W.; Manufacturer PN: RC0402JR-073R3L; Manufacturer: YAGEO; Wattage: 1/16W; Priority: A
R28 = R_0
R29 R30 R34 R35 = RESISTOR: as R79 on sheet 11
R32 = RESISTOR: 通用厚膜电阻,51K,+/-1%,R0402,1/16W.; Manufacturer: YAGEO; RK PN: RC0402FR-0751KL; Priority: A; Wattage: 1/16W
R33 = RESISTOR: 通用厚膜电阻,100K,+/-5%,R0402,1/16W.; Manufacturer: YAGEO; RK PN: RC0402JR-07100KL; Priority: A; Wattage: 1/16W
SW2 SW4 = KEY_0: SMD按键6X6高度9MM; Manufacturer Part Number: KEY_5X5; Manufacturer: 旺科达; Priority: A
SW3 = KEY_0: SMD按键6X6高度9MM; Manufacturer: 旺科达; RK PN: KEY_5X5; Priority: A
U5 = DCDC_NB679: 26 V, Low Iq, High Current, Fixed 5 V-8 A Synchronous Buck Converter with 100 mA LDO;; Manufacturer: MPS （美国芯源）

## Sheet 04.SchDoc
size 297 x 209 mm
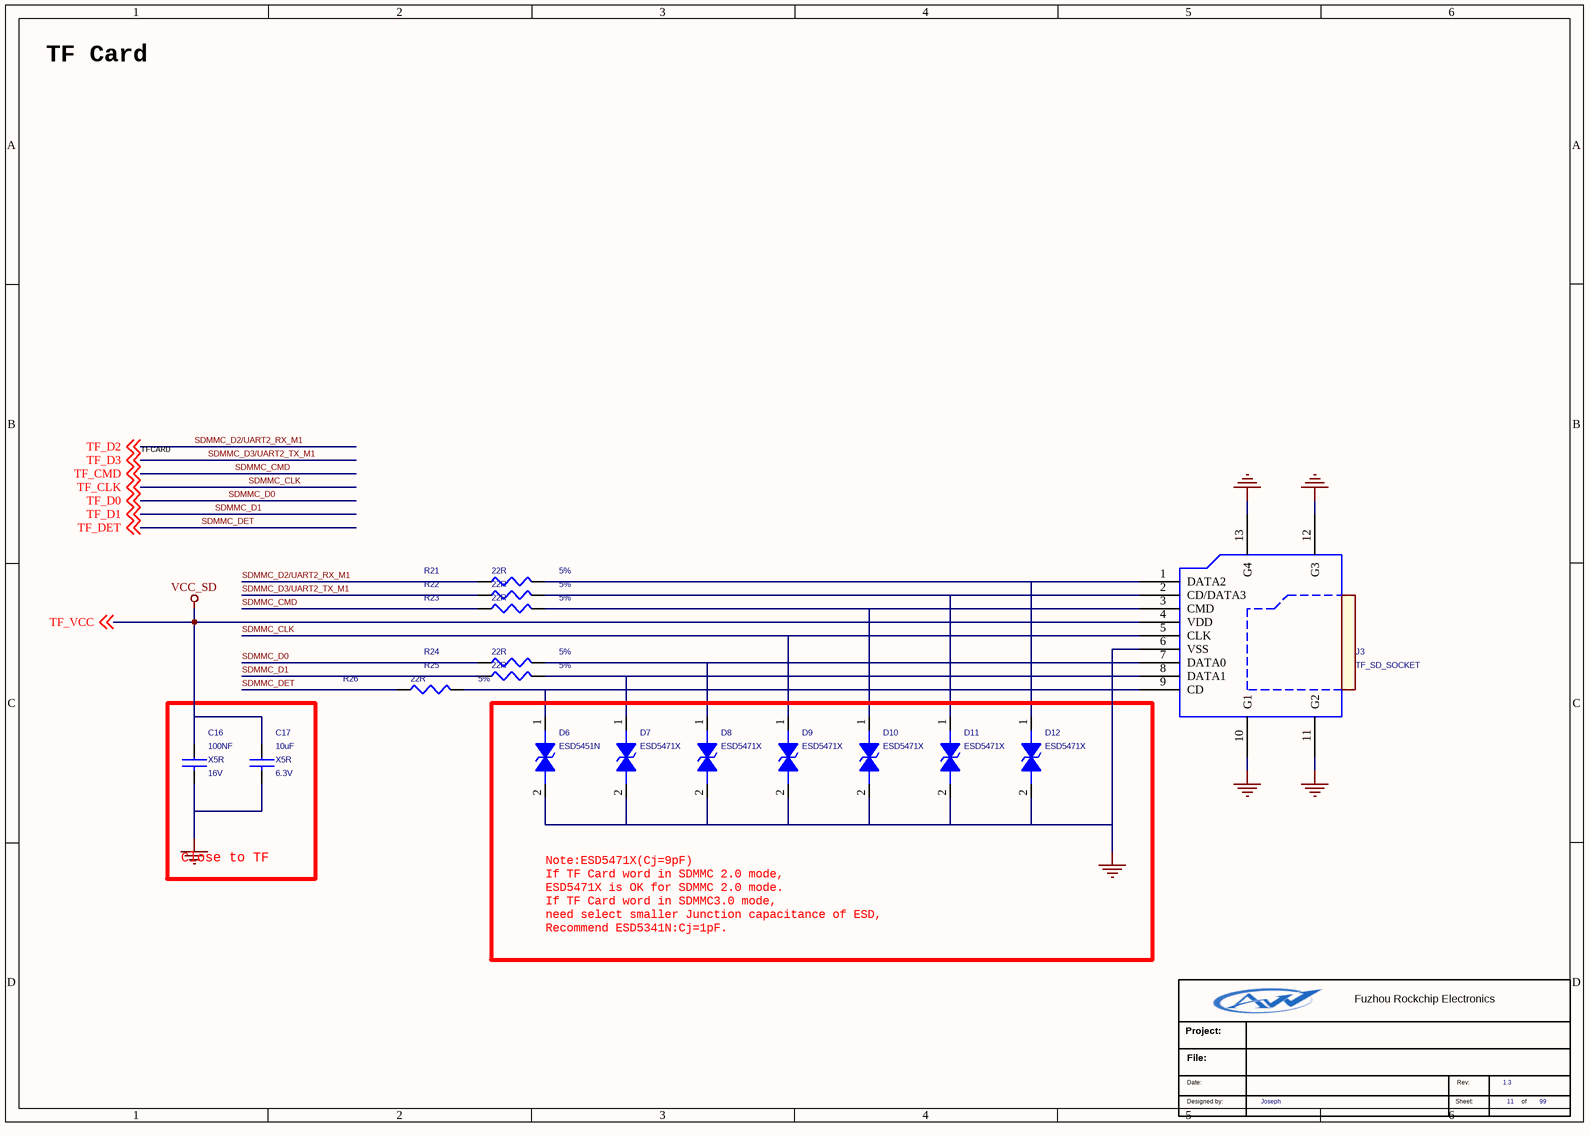
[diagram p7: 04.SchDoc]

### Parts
*  Revision: 1.3  Designer: Joseph  Schematic Page Number: 11  Schematic Page Count: 99  (hidden comment: Rockchip)  (graphical)
C16  100NF  Voltage: 16V  Dielectric: X5R  [C0402]
C17  10uF  Voltage: 6.3V  Dielectric: X5R  [C0603]
D6  ESD5451N  [ESD0402]
D7  ESD5471X  [ESD0402]
D8  ESD5471X  [ESD0402]
D9  ESD5471X  [ESD0402]
D10  ESD5471X  [ESD0402]
D11  ESD5471X  [ESD0402]
D12  ESD5471X  [ESD0402]
J3  TF_SD_SOCKET  [TF-CKT01-009D]
R21  22R  Tolerance: 5%  [R0402]
R22  22R  Tolerance: 5%  [R0402]
R23  22R  Tolerance: 5%  [R0402]
R24  22R  Tolerance: 5%  [R0402]
R25  22R  Tolerance: 5%  [R0402]
R26  22R  Tolerance: 5%  [R0402]

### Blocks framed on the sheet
Close to TF: C16 C17

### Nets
GND: C16.2 C17.2 D6.2 D7.2 D8.2 D9.2 D10.2 D11.2 D12.2 J3.6(VSS) J3.10(G1) J3.11(G2) J3.12(G3) J3.13(G4)  [project net ABLU0]
VCC_SD: C16.1 C17.1 J3.4(VDD) ; off-sheet TF_VCC  [also labelled TF_VCC]
SDMMC_CLK: D9.1 J3.5(CLK) ; off-sheet TF_CLK  [also labelled TF_CLK]
SDMMC_CMD: R23.1 ; off-sheet TF_CMD  [also labelled TF_CMD]
SDMMC_D0: R24.1 ; off-sheet TF_D0  [also labelled TF_D0]
SDMMC_D1: R25.1 ; off-sheet TF_D1  [also labelled TF_D1]
SDMMC_D2/UART2_RX_M1: R21.1 ; off-sheet TF_D2  [also labelled TF_D2]
SDMMC_D3/UART2_TX_M1: R22.1 ; off-sheet TF_D3  [also labelled TF_D3]
SDMMC_DET: R26.1 ; off-sheet TF_DET  [also labelled TF_DET]
NetD6_1: D6.1 J3.9(CD) R26.2
NetD7_1: D7.1 J3.8(DATA1) R25.2
NetD8_1: D8.1 J3.7(DATA0) R24.2
NetD10_1: D10.1 J3.3(CMD) R23.2
NetD11_1: D11.1 J3.2(CD/DATA3) R22.2
NetD12_1: D12.1 J3.1(DATA2) R21.2

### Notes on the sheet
- TF Card
- TFCARD
- Note:ESD5471X(Cj=9pF)
  If TF Card word in SDMMC 2.0 mode,
  ESD5471X is OK for SDMMC 2.0 mode.
  If TF Card word in SDMMC3.0 mode,
  need select smaller Junction capacitance of ESD,
  Recommend ESD5341N:Cj=1pF.

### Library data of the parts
* = Rockchip: Revcode: V1.3; Page Number: 4
C16 = CAP NP: cap,100.00nF,+/-10%,16V,X5R,C0402; Manufacturer: TDK; Number: 37; RK PN: C1005X5R1C104K050BA; Priority: A; Tolerance: 10%; C_Voltage: 6.3V
C17 = CAP NP: cap,10.00uF,+/-10%,6.3V,X5R,C0603; Manufacturer: TDK; RK PN: C1608X5R0J106K080AB; Priority: A; Tolerance: 10%
D6 = DIODE BI_DIR TRIG: as ED5 on sheet 10
D7-D12 = DIODE BI_DIR TRIG: 1-Line, Bi-directional, Transient Voltage Suppressors.9pF.; Manufacturer: WillSemi(韦尔半导体); Priority: A
J3 = TF_SD_SOCKET_0: TF card connector,9pin,SMT
R21 R25 R26 = RESISTOR: as R63 on sheet 10
R22-R24 = RESISTOR: as R65 on sheet 10

## Sheet 03.SchDoc
size 420 x 297 mm
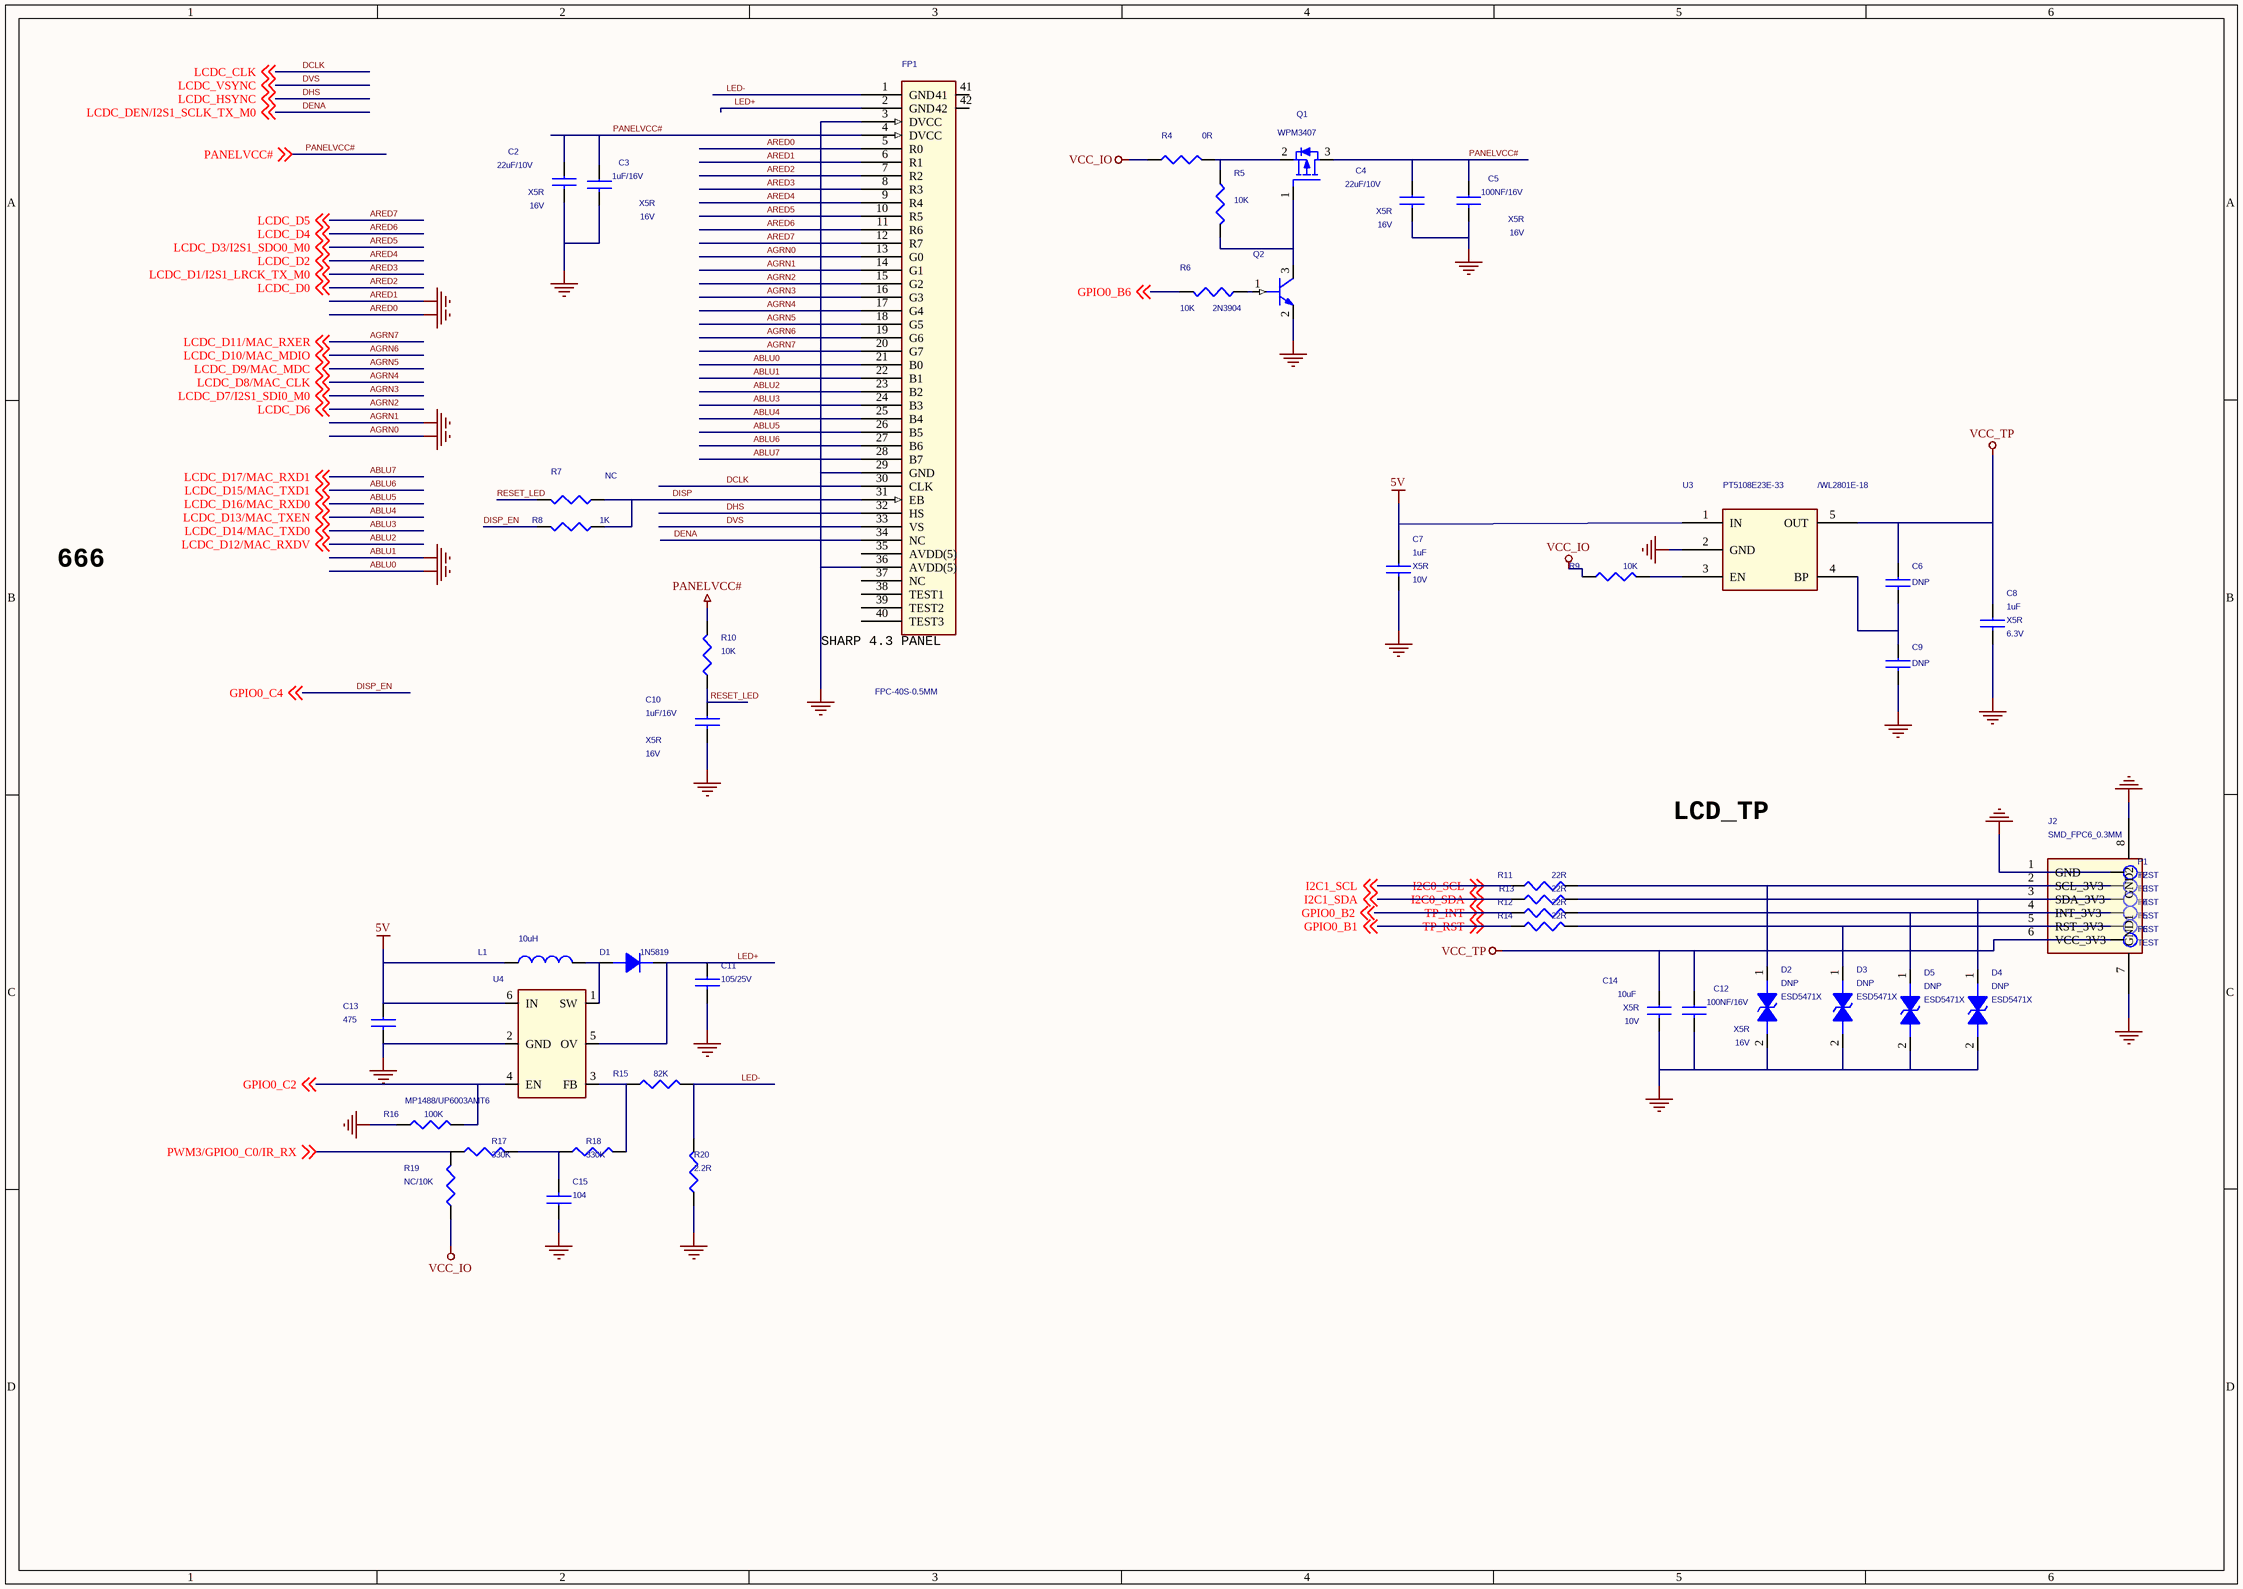
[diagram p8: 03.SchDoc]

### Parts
C2  22uF/10V  Dielectric: X5R  Voltage: 16V  [C0603]
C3  1uF/16V  Voltage: 16V  Dielectric: X5R  [C0402]
C4  22uF/10V  Voltage: 16V  Dielectric: X5R  [C0603]
C5  100NF/16V  Dielectric: X5R  Voltage: 16V  [C0402]
C6  DNP  [C0201]
C7  1uF  Voltage: 10V  Dielectric: X5R  [C0201]
C8  1uF  Voltage: 6.3V  Dielectric: X5R  [C0201]
C9  DNP  [C0201]
C10  1uF/16V  Voltage: 16V  Dielectric: X5R  [C0402]
C11  105/25V  [C0805]
C12  100NF/16V  Dielectric: X5R  Voltage: 16V  [C0402]
C13  475  [C0603]
C14  10uF  Dielectric: X5R  Voltage: 10V  [C0603]
C15  104  [C0603]
D1  1N5819  [SOD123]
D2  ESD5471X  OPTION: DNP  [ESD0402]
D3  ESD5471X  OPTION: DNP  [ESD0402]
D4  ESD5471X  OPTION: DNP  [ESD0402]
D5  ESD5471X  OPTION: DNP  [ESD0402]
FP1  FPC-40S-0.5MM  [CON30]
J2  SMD_FPC6_0.3MM  [DIP3_1X3_2R54]
L1  10uH  [CDRH3D16]
P1  TEST  [TEST]
P2  TEST  [TEST]
P3  TEST  [TEST]
P4  TEST  [TEST]
P5  TEST  [TEST]
P6  TEST  [TEST]
Q1  WPM3407  [SOT-23]
Q2  2N3904  [SOT-23]
R4  0R  [R0402]
R5  10K  [R0402]
R6  10K  [R0402]
R7  NC  [R0402]
R8  1K  [R0402]
R9  10K  [R0402]
R10  10K  [R0402]
R11  22R  [R0402]
R12  22R  [R0402]
R13  22R  [R0402]
R14  22R  [R0402]
R15  82K  [R0402]
R16  100K  [R0402]
R17  330K  [R0402]
R18  330K  [R0402]
R19  NC/10K  [R0402]
R20  2.2R  [R0805]
U3  PT5108E23E-33  OPTION: /WL2801E-18  [SOT_23_5]
U4  MP1488/UP6003AMT6  [SOT-23-6]

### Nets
5V: C7.1 C13.1 L1.1 U3.1(IN) U4.6(IN)
ABLU0: C2.2 C3.2 C4.2 C5.2 C7.2 C8.2 C9.2 C10.2 C11.2 C12.2 C13.2 C14.2 C15.1 D2.2 D3.2 D4.2 D5.2 FP1.3(DVCC) FP1.5(R0) FP1.6(R1) FP1.13(G0) FP1.14(G1) FP1.21(B0) FP1.22(B1) FP1.29(GND) FP1.36(AVDD(5)) J2.1(GND) J2.7(GND1) J2.8(GND2) P1.1 Q2.2(EMITTER) R16.1 R20.2 U3.2(GND) U4.2(GND)  [also labelled ABLU1, AGRN0, AGRN1, ARED0, ARED1, GND]
PANELVCC#: C2.1 C3.1 C4.1 C5.1 FP1.4(DVCC) Q1.3(DRAIN) R10.1 ; off-sheet PANELVCC#
VCC_IO: R4.1 R9.1 R19.2  [project net VCC3V3_SYS]
VCC_TP: C6.1 C8.1 C12.1 C14.1 J2.6(VCC_3V3) P6.1 U3.5(OUT)
ABLU2: FP1.23(B2) ; off-sheet LCDC_D12/MAC_RXDV  [also labelled LCDC_D12/MAC_RXDV]
ABLU3: FP1.24(B3) ; off-sheet LCDC_D14/MAC_TXD0  [also labelled LCDC_D14/MAC_TXD0]
ABLU4: FP1.25(B4) ; off-sheet LCDC_D13/MAC_TXEN  [also labelled LCDC_D13/MAC_TXEN]
ABLU5: FP1.26(B5) ; off-sheet LCDC_D16/MAC_RXD0  [also labelled LCDC_D16/MAC_RXD0]
ABLU6: FP1.27(B6) ; off-sheet LCDC_D15/MAC_TXD1  [also labelled LCDC_D15/MAC_TXD1]
ABLU7: FP1.28(B7) ; off-sheet LCDC_D17/MAC_RXD1  [also labelled LCDC_D17/MAC_RXD1]
AGRN2: FP1.15(G2) ; off-sheet LCDC_D6  [also labelled LCDC_D6]
AGRN3: FP1.16(G3) ; off-sheet LCDC_D7/I2S1_SDI0_M0  [also labelled LCDC_D7/I2S1_SDI0_M0]
AGRN4: FP1.17(G4) ; off-sheet LCDC_D8/MAC_CLK  [also labelled LCDC_D8/MAC_CLK]
AGRN5: FP1.18(G5) ; off-sheet LCDC_D9/MAC_MDC  [also labelled LCDC_D9/MAC_MDC]
AGRN6: FP1.19(G6) ; off-sheet LCDC_D10/MAC_MDIO  [also labelled LCDC_D10/MAC_MDIO]
AGRN7: FP1.20(G7) ; off-sheet LCDC_D11/MAC_RXER  [also labelled LCDC_D11/MAC_RXER]
ARED2: FP1.7(R2) ; off-sheet LCDC_D0  [also labelled LCDC_D0]
ARED3: FP1.8(R3) ; off-sheet LCDC_D1/I2S1_LRCK_TX_M0  [also labelled LCDC_D1/I2S1_LRCK_TX_M0]
ARED4: FP1.9(R4) ; off-sheet LCDC_D2  [also labelled LCDC_D2]
ARED5: FP1.10(R5) ; off-sheet LCDC_D3/I2S1_SDO0_M0  [also labelled LCDC_D3/I2S1_SDO0_M0]
ARED6: FP1.11(R6) ; off-sheet LCDC_D4  [also labelled LCDC_D4]
ARED7: FP1.12(R7) ; off-sheet LCDC_D5  [also labelled LCDC_D5]
DCLK: FP1.30(CLK) ; off-sheet LCDC_CLK  [also labelled LCDC_CLK]
DENA: FP1.34(NC) ; off-sheet LCDC_DEN/I2S1_SCLK_TX_M0  [also labelled LCDC_DEN/I2S1_SCLK_TX_M0]
DHS: FP1.32(HS) ; off-sheet LCDC_HSYNC  [also labelled LCDC_HSYNC]
DISP: FP1.31(EB) R7.1 R8.1
DISP_EN: R8.2 ; off-sheet GPIO0_C4  [also labelled GPIO0_C4]
DVS: FP1.33(VS) ; off-sheet LCDC_VSYNC  [also labelled LCDC_VSYNC]
GPIO0_B1: R14.1 ; off-sheet TP_RST, off-sheet GPIO0_B1  [also labelled TP_RST]
GPIO0_B2: R12.1 ; off-sheet TP_INT, off-sheet GPIO0_B2  [also labelled TP_INT]
GPIO0_B6: R6.2 ; off-sheet GPIO0_B6
GPIO0_C2: R16.2 U4.4(EN) ; off-sheet GPIO0_C2
I2C0_SCL: R11.1 ; off-sheet I2C0_SCL, off-sheet I2C1_SCL  [also labelled I2C1_SCL]
I2C0_SDA: R13.1 ; off-sheet I2C0_SDA, off-sheet I2C1_SDA  [also labelled I2C1_SDA]
LED+: C11.1 D1.2(K) FP1.2(GND) U4.5(OV)
LED-: FP1.1(GND) R15.2 R20.1
PWM3/GPIO0_C0/IR_RX: R17.1 R19.1 ; off-sheet PWM3/GPIO0_C0/IR_RX
RESET_LED: C10.1 R7.2 R10.2
NetC6_2: C6.2 C9.1 U3.4(BP)
NetC15_2: C15.2 R17.2 R18.1
NetD1_1: D1.1(A) L1.2 U4.1(SW)
NetD2_1: D2.1 J2.2(SCL_3V3) P2.1 R11.2
NetD3_1: D3.1 J2.5(RST_3V3) P5.1 R14.2
NetD4_1: D4.1 J2.3(SDA_3V3) P3.1 R13.2
NetD5_1: D5.1 J2.4(INT_3V3) P4.1 R12.2
NetQ1_1: Q1.1(GATE) Q2.3(COLLECTOR) R5.2
NetQ1_2: Q1.2(SOURCE) R4.2 R5.1
NetQ2_1: Q2.1(BASE) R6.1
NetR9_2: R9.2 U3.3(EN)
NetR15_1: R15.1 R18.2 U4.3(FB)

Not connected (* = marked no-connect by the designer): FP1 35(AVDD(5)) 37(NC) 38(TEST1) 39(TEST2) 40(TEST3) 41 42

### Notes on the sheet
- 666
- (near FP1) SHARP 4.3 PANEL
- LCD_TP

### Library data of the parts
C2 = CAP NP: cap,22.00uF,+/-10%,10V,X5R,C0805; Manufacturer: TDK; RK PN: C2012X5R1A226K125AB; Priority: A; Tolerance: 10%
C3 C10 = CAP NP: as C67 on sheet 11
C4 = CAP NP: cap,22.00uF,+/-10%,10V,X5R,C0805; Manufacturer PN: C2012X5R1A226K125AB; Manufacturer: TDK; Tolerance: 10%; Priority: A
C5 C12 = CAP NP: as C66 on sheet 11
C6 C9 = CAP NP: Did Not Place.; Manufacturer PN: DNP0402; Priority: A
C7 = CAP NP: cap,1.00uF,+/-10%,10V,X5R,C0402; Manufacturer: TDK; RK PN: C1005X5R1A105K050BB; Priority: A; C_Voltage: 6.3V; Tolerance: 10%
C8 = CAP NP: cap,1.00uF,+/-10%,6.3V,X5R,C0402; Manufacturer PN: C1005X5R0J105K050BB; Manufacturer: TDK; Tolerance: 10%; Priority: A
C11 = C0805: RoHS CHIP CAP 1uF ±10% X7R/25; BOM_VALUE: 0; BOM_TYPE: 30
C13 = C0603: RoHS CHIP CAP 4.7uF +10/-10% X5R; BOM_TYPE: 30; BOM_VALUE: 0
C14 = CAP NP: cap,10.00uF,+/-10%,10V,X5R,C0603; Manufacturer: TDK; RK PN: C1608X5R1A106K080AC; Priority: A; Tolerance: 10%
C15 = C0603: RoHS CHIP CAP 0.1uF +10/-10% X7R; BOM_TYPE: 30; BOM_VALUE: 0
D1 = DIODE: RoHS 1.0A SURFACE MOUNT SCHOTTKY BARRIER RECTIFIER 1N5819; BOM_VALUE: 0; ROOM: CHG; BOM_TYPE: 50
D2 D3 D5 = DIODE BI_DIR TRIG: 1-Line, Bi-directional, Transient Voltage Suppressors.17.5pF.; Manufacturer PN: ESD5451N; Manufacturer: WillSemi(韦尔半导体); Priority: A
D4 = DIODE BI_DIR TRIG: 1-Line, Bi-directional, Transient Voltage Suppressors.17.5pF.; Manufacturer: WillSemi(韦尔半导体); RK PN: ESD5451N; Priority: A
FP1 = LCDPANEL(CHA1_0
J2 = CON3_1: 单排3PIN（间距2.54mm）不带防护墙的插针; Manufacturer Part Number: CON3M_1X3_2R54_V; Priority: A
L1 = L_CDRH3D16: CoilInd,Shielded(SHLD),10uH@100KHz,+/-30%,0.5A,51mOhm,SMD,4.0*4.0*2.0; BOM_TYPE: 40; BOM_VALUE: 0
P1-P6 = TESTPOINT1
Q1 = MOSFET N_2
Q2 = Q2N3508_3
R4 R7 R8 = RESISTOR
R5 R6 = RES: Tolerance: 5%
R9 R11 R12 R14 R15 = R0402: ROHS CHIP RES 82K 1/16W 5%; BOM_TYPE: 20; BOM_VALUE: 0
R10 = R: Part Number: 01054F4722; Approval No: 1404Y133,1404X006,14043209,24055429
R13 = R0402: ROHS CHIP RES 82K 1/16W 5%; BOM_VALUE: 0; BOM_TYPE: 20
R16 = R0402: ROHS CHIP RES 100K 1/16W +/-5%; BOM_TYPE: 20; BOM_VALUE: 0
R17 R18 = R0402: ROHS CHIP RES 330K 1/16W 5%; BOM_VALUE: 0; BOM_TYPE: 20
R19 = RESISTOR_1: NC/ROHS CHIP RES 10K 1/16W +/-5%; BOM_VALUE: 0; BOM_TYPE: 20
R20 = RESISTOR_0: ROHS CHIP RES 2.2R 1/4W 5%; BOM_TYPE: 20; BOM_VALUE: 0
U3 = LDO_PT5108: High-PSRR 600mA LDO.Output1.8V.; Manufacturer PN: PT5108E23E-18; Manufacturer: Powtech（华润矽威）; Priority: A
U4 = U_MP3202: MP1488/UP6003AMT6  Fixed Frequency White LED Driver; BOM_VALUE: 8; BOM_TYPE: 10

## Sheet 02.SchDoc
size 246 x 182 mm
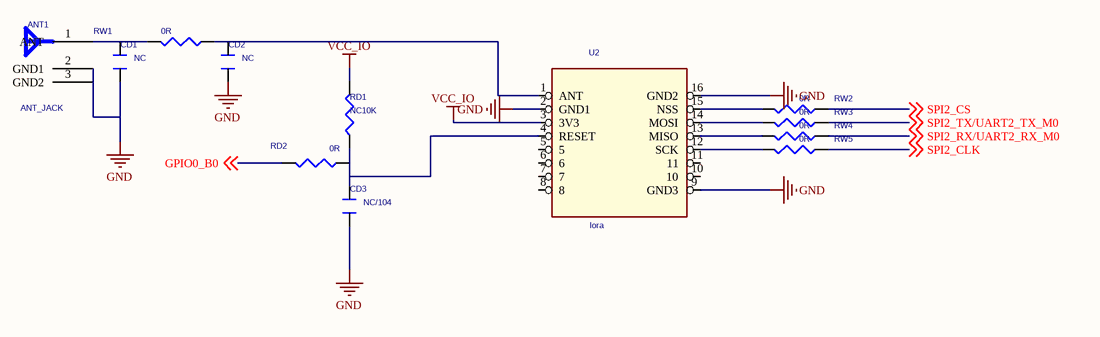
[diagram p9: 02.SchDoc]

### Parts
ANT1  ANT_JACK  [ANT_JACK]
CD1  NC  [C0402]
CD2  NC  [C0402]
CD3  NC/104  [C0402]
RD1  NC10K  [R0402]
RD2  0R  [R0402]
RW1  0R  [R0402]
RW2  0R  [R0402]
RW3  0R  [R0402]
RW4  0R  [R0402]
RW5  0R  [R0402]
U2  lora  [lora]

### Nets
GND: ANT1.2(GND1) ANT1.3(GND2) CD1.1 CD2.1 CD3.1 U2.2(GND1) U2.9(GND3) U2.16(GND2)  [project net ABLU0]
VCC_IO: RD1.2 U2.3(3V3)  [project net VCC3V3_SYS]
GPIO0_B0: RD2.2 ; off-sheet GPIO0_B0
SPI2_CLK: RW5.2 ; off-sheet SPI2_CLK
SPI2_CS: RW2.2 ; off-sheet SPI2_CS
SPI2_RX/UART2_RX_M0: RW4.2 ; off-sheet SPI2_RX/UART2_RX_M0
SPI2_TX/UART2_TX_M0: RW3.2 ; off-sheet SPI2_TX/UART2_TX_M0
NetANT1_1: ANT1.1(ANT) CD1.2 RW1.2
NetCD2_2: CD2.2 RW1.1 U2.1(ANT)
NetCD3_2: CD3.2 RD1.1 RD2.1 U2.4(RESET)
NetRW2_1: RW2.1 U2.15(NSS)
NetRW3_1: RW3.1 U2.14(MOSI)
NetRW4_1: RW4.1 U2.13(MISO)
NetRW5_1: RW5.1 U2.12(SCK)

Not connected (* = marked no-connect by the designer): U2 5 6 7 8 10 11

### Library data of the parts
ANT1 = ANT_1P2G: 焊接式WIFI天线座，单频; Manufacturer: Rockchip; Priority: A
CD1 CD3 = CAPACITOR_0: PAGE: 1; ROOM: LPDDR3
CD2 = CAPACITOR_0: ROOM: LPDDR3; PAGE: 1
RD1 RD2 = ?_0: ROOM: LPDDR3
RW1 RW3-RW5 = R-R0402: mypage: 08; ROOM: EMMC
RW2 = R-R0402: ROOM: EMMC; mypage: 08

## Sheet 01.SchDoc
size 594 x 420 mm
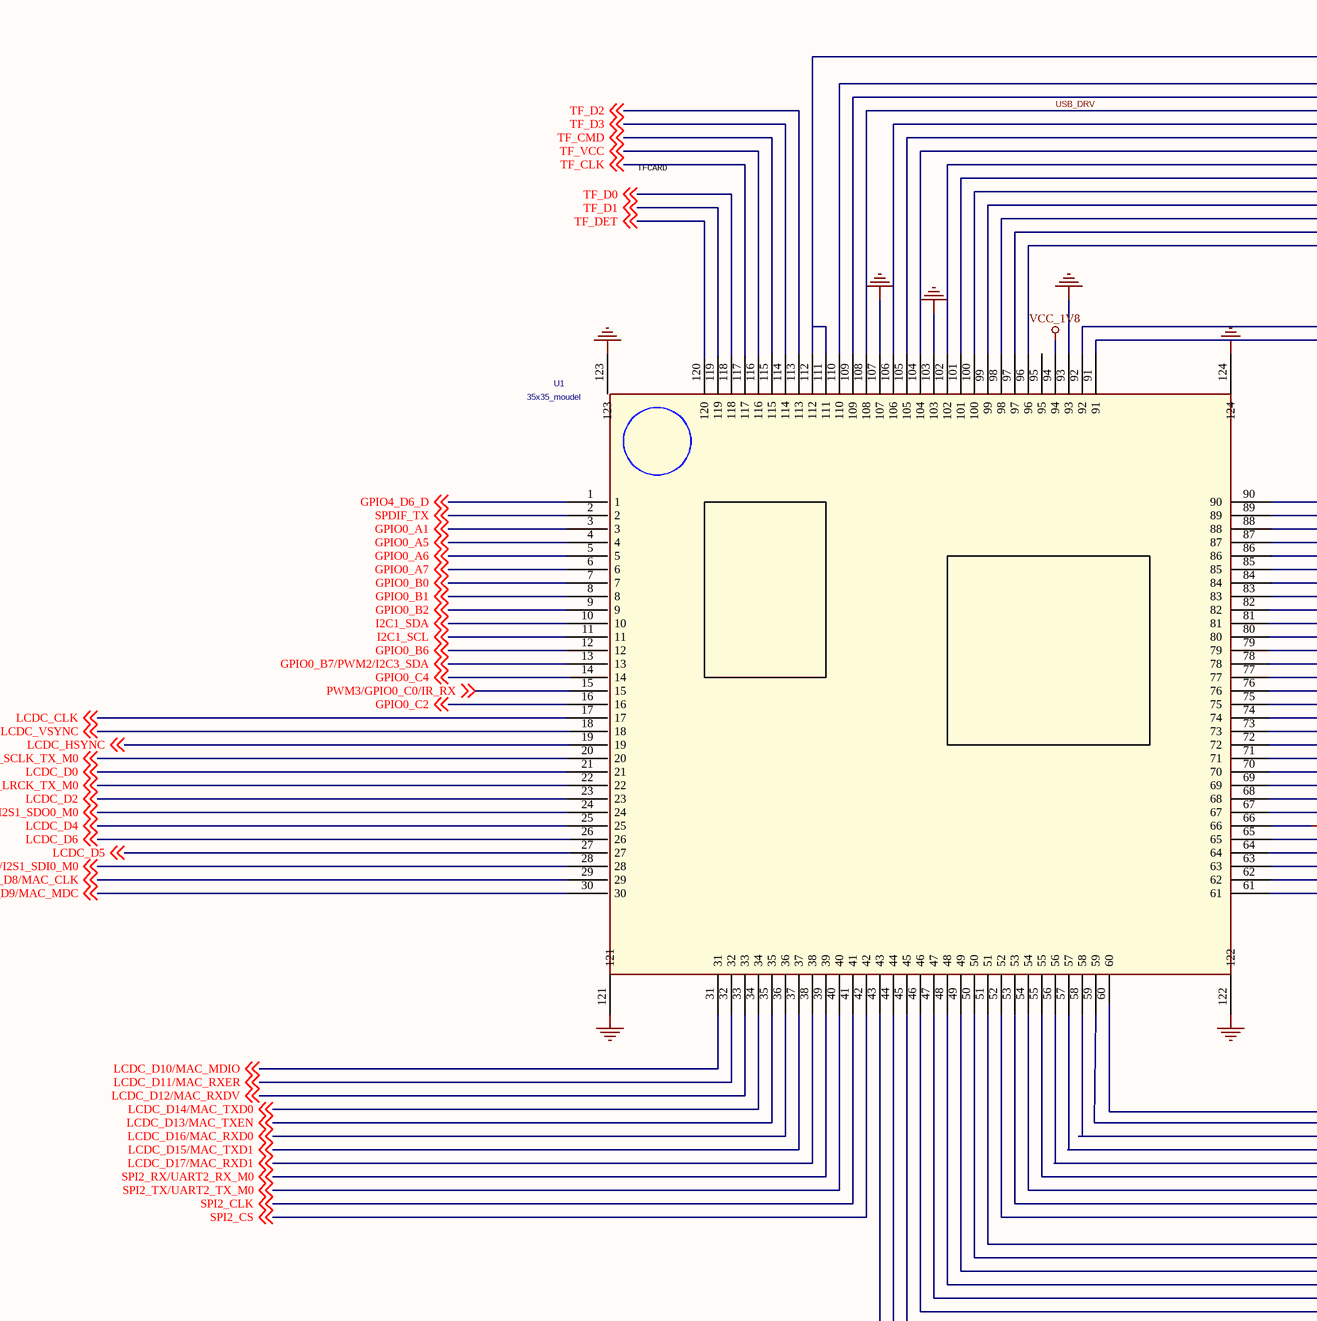
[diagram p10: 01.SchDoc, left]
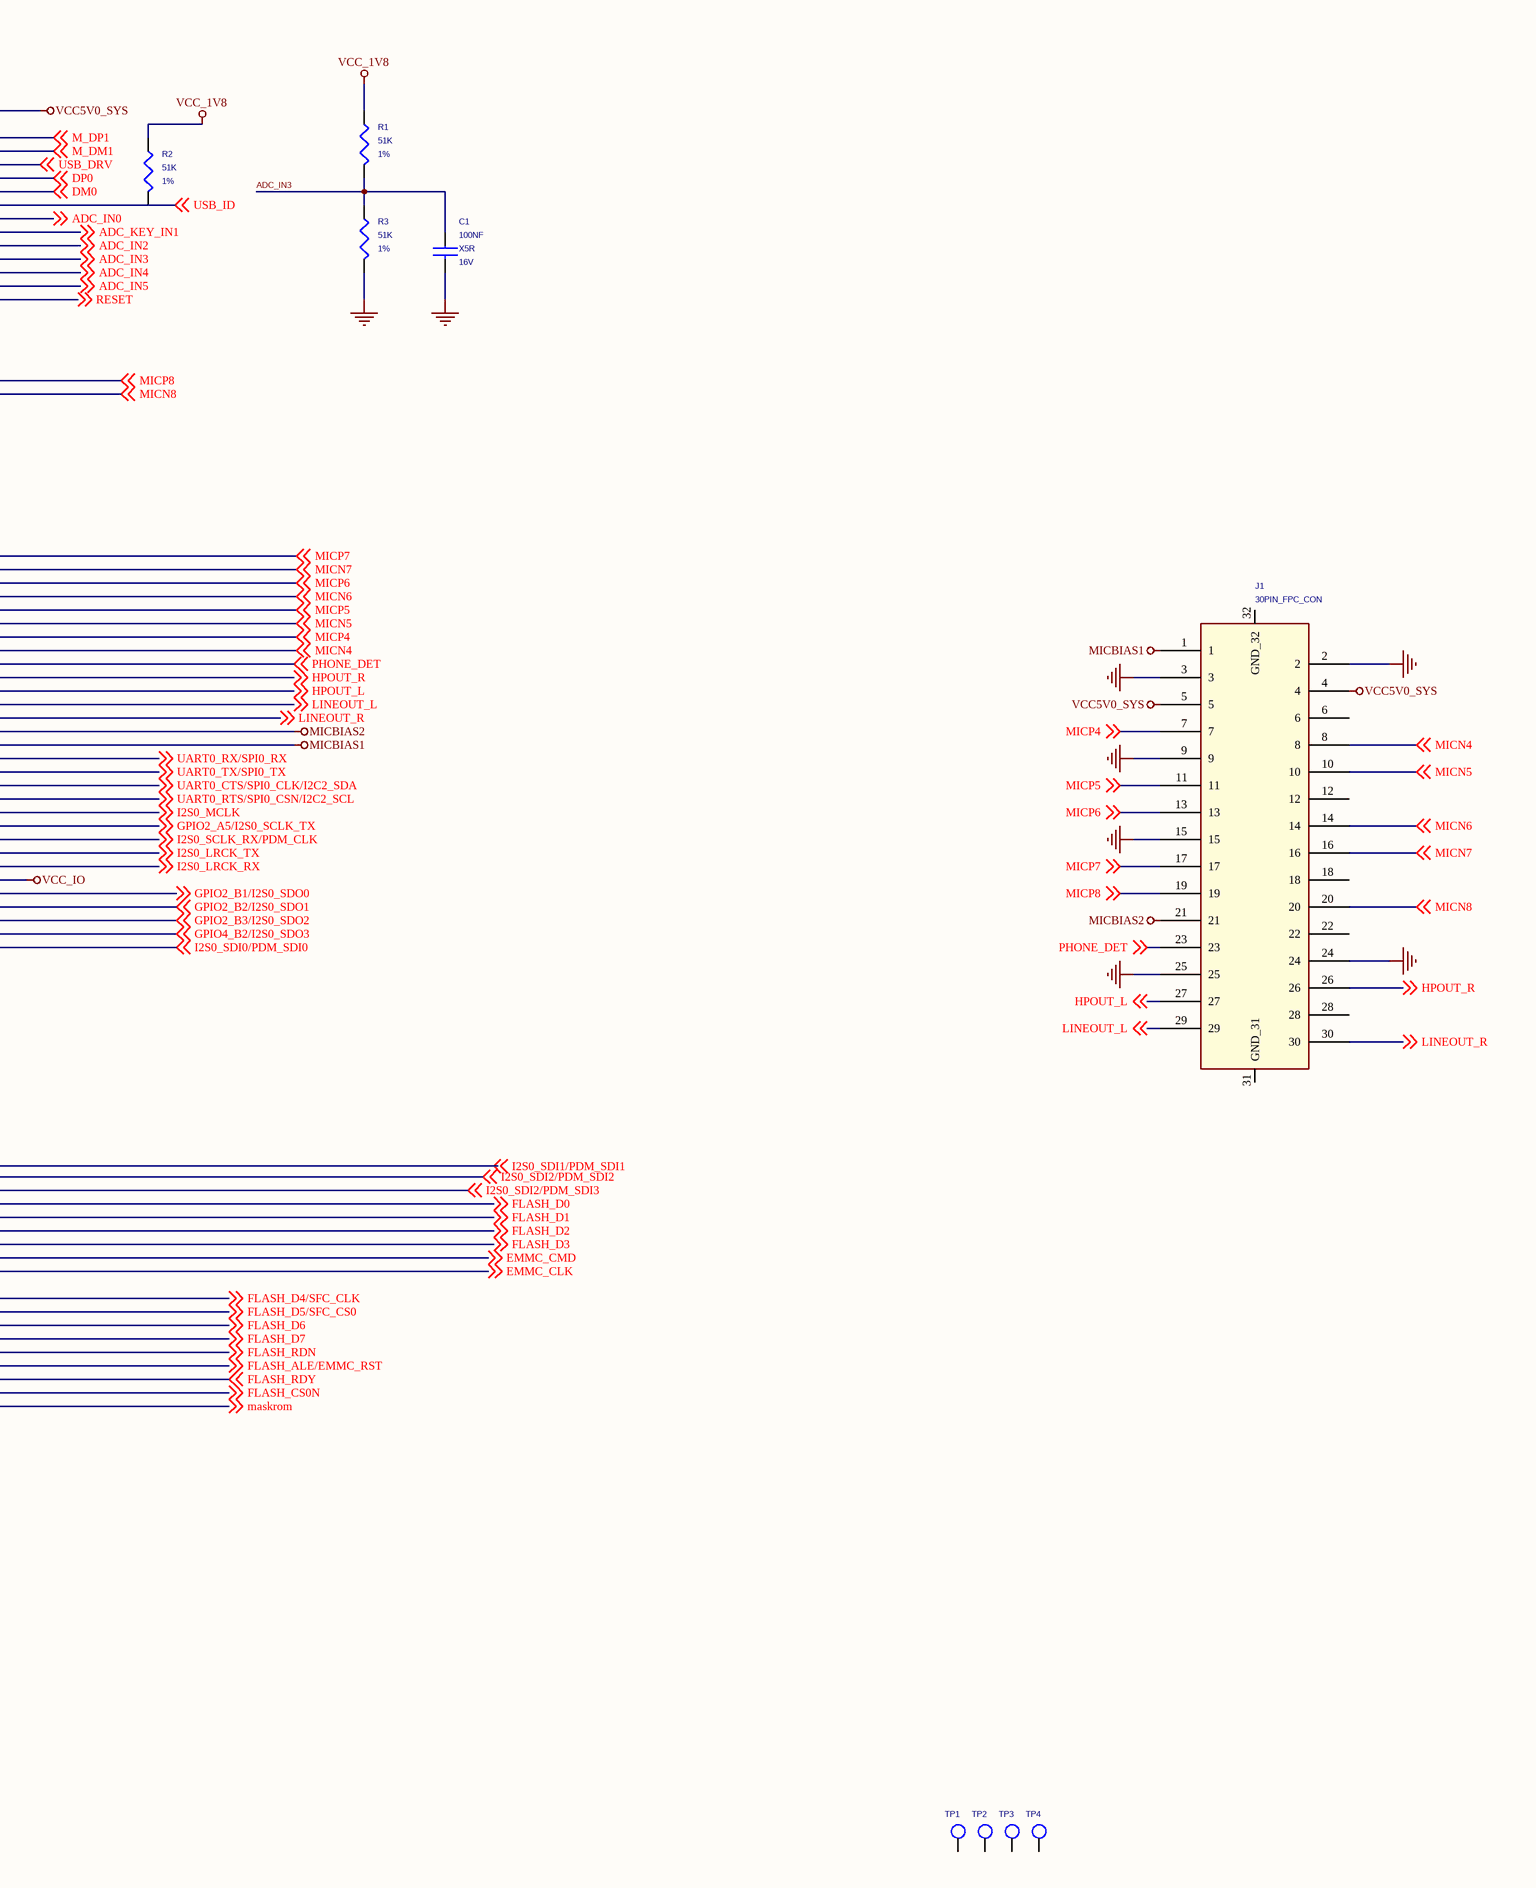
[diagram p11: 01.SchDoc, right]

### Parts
C1  100NF  Dielectric: X5R  Voltage: 16V  [C0402]
J1  30PIN_FPC_CON  [FPC30R_0R50_DOWN]
R1  51K  Tolerance: 1%  [R0402]
R2  51K  Tolerance: 1%  [R0402]
R3  51K  Tolerance: 1%  [R0402]
TP1  TESTPOINT1  [TEST]  (value not drawn)
TP2  TESTPOINT1  [TEST]  (value not drawn)
TP3  TESTPOINT1  [TEST]  (value not drawn)
TP4  TESTPOINT1  [TEST]  (value not drawn)
U1  35x35_moudel  [35x35_moudel]

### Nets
GND: C1.2 J1.2 J1.3 J1.9 J1.15 J1.24 J1.25 R3.2 U1.93 U1.103 U1.107 U1.121 U1.122 U1.123 U1.124  [project net ABLU0]
MICBIAS1: J1.1 U1.76
MICBIAS2: J1.21 U1.77
TF_VCC: U1.116 ; off-sheet TF_VCC  [project net VCC_SD]
VCC5V0_SYS: J1.4 J1.5 U1.111 U1.112  [project net 5V]
VCC_1V8: R1.1 R2.1 U1.94
VCC_IO: U1.66  [project net VCC3V3_SYS]
ADC_IN0: U1.102 ; off-sheet ADC_IN0
ADC_IN2: U1.100 ; off-sheet ADC_IN2
ADC_IN3: C1.1 R1.2 R3.1 U1.99 ; off-sheet ADC_IN3  [project net ADC_HW_ID1]
ADC_IN4: U1.98 ; off-sheet ADC_IN4
ADC_IN5: U1.97 ; off-sheet ADC_IN5
ADC_KEY_IN1: U1.101 ; off-sheet ADC_KEY_IN1
DM0: U1.105 ; off-sheet DM0  [project net USB-DM0]
DP0: U1.106 ; off-sheet DP0  [project net USB-DP0]
EMMC_CLK: U1.52 ; off-sheet EMMC_CLK
EMMC_CMD: U1.53 ; off-sheet EMMC_CMD
FLASH_ALE/EMMC_RST: U1.46 ; off-sheet FLASH_ALE/EMMC_RST
FLASH_CS0N: U1.44 ; off-sheet FLASH_CS0N
FLASH_D0: U1.57 ; off-sheet FLASH_D0  [project net EMMC_D0]
FLASH_D1: U1.56 ; off-sheet FLASH_D1  [project net EMMC_D1]
FLASH_D2: U1.55 ; off-sheet FLASH_D2  [project net EMMC_D2]
FLASH_D3: U1.54 ; off-sheet FLASH_D3  [project net EMMC_D3]
FLASH_D4/SFC_CLK: U1.51 ; off-sheet FLASH_D4/SFC_CLK  [project net EMMC_D4]
FLASH_D5/SFC_CS0: U1.50 ; off-sheet FLASH_D5/SFC_CS0  [project net EMMC_D5]
FLASH_D6: U1.49 ; off-sheet FLASH_D6  [project net EMMC_D6]
FLASH_D7: U1.48 ; off-sheet FLASH_D7  [project net EMMC_D7]
FLASH_RDN: U1.47 ; off-sheet FLASH_RDN  [project net MIC_LED_EN]
FLASH_RDY: U1.45 ; off-sheet FLASH_RDY
GPIO0_A1: U1.3 ; off-sheet GPIO0_A1
GPIO0_A5: U1.4 ; off-sheet GPIO0_A5
GPIO0_A6: U1.5 ; off-sheet GPIO0_A6
GPIO0_A7: U1.6 ; off-sheet GPIO0_A7
GPIO0_B0: U1.7 ; off-sheet GPIO0_B0
GPIO0_B1: U1.8 ; off-sheet GPIO0_B1
GPIO0_B2: U1.9 ; off-sheet GPIO0_B2
GPIO0_B6: U1.12 ; off-sheet GPIO0_B6
GPIO0_B7/PWM2/I2C3_SDA: U1.13 ; off-sheet GPIO0_B7/PWM2/I2C3_SDA
GPIO0_C2: U1.16 ; off-sheet GPIO0_C2
GPIO0_C4: U1.14 ; off-sheet GPIO0_C4  [project net DISP_EN]
GPIO2_A5/I2S0_SCLK_TX: U1.70 ; off-sheet GPIO2_A5/I2S0_SCLK_TX
GPIO2_B1/I2S0_SDO0: U1.65 ; off-sheet GPIO2_B1/I2S0_SDO0
GPIO2_B2/I2S0_SDO1: U1.64 ; off-sheet GPIO2_B2/I2S0_SDO1
GPIO2_B3/I2S0_SDO2: U1.63 ; off-sheet GPIO2_B3/I2S0_SDO2
GPIO4_B2/I2S0_SDO3: U1.62 ; off-sheet GPIO4_B2/I2S0_SDO3
GPIO4_D6_D: U1.1 ; off-sheet GPIO4_D6_D
HPOUT_L: J1.27 U1.80 ; off-sheet HPOUT_L
HPOUT_R: J1.26 U1.81 ; off-sheet HPOUT_R
I2C1_SCL: U1.11 ; off-sheet I2C1_SCL  [project net I2C0_SCL]
I2C1_SDA: U1.10 ; off-sheet I2C1_SDA  [project net I2C0_SDA]
I2S0_LRCK_RX: U1.67 ; off-sheet I2S0_LRCK_RX
I2S0_LRCK_TX: U1.68 ; off-sheet I2S0_LRCK_TX
I2S0_MCLK: U1.71 ; off-sheet I2S0_MCLK
I2S0_SCLK_RX/PDM_CLK: U1.69 ; off-sheet I2S0_SCLK_RX/PDM_CLK
I2S0_SDI0/PDM_SDI0: U1.61 ; off-sheet I2S0_SDI0/PDM_SDI0
I2S0_SDI1/PDM_SDI1: U1.60 ; off-sheet I2S0_SDI1/PDM_SDI1
I2S0_SDI2/PDM_SDI2: U1.59 ; off-sheet I2S0_SDI2/PDM_SDI2
I2S0_SDI2/PDM_SDI3: U1.58 ; off-sheet I2S0_SDI2/PDM_SDI3
LCDC_CLK: U1.17 ; off-sheet LCDC_CLK  [project net DCLK]
LCDC_D0: U1.21 ; off-sheet LCDC_D0  [project net ARED2]
LCDC_D1/I2S1_LRCK_TX_M0: U1.22 ; off-sheet LCDC_D1/I2S1_LRCK_TX_M0  [project net ARED3]
LCDC_D2: U1.23 ; off-sheet LCDC_D2  [project net ARED4]
LCDC_D3/I2S1_SDO0_M0: U1.24 ; off-sheet LCDC_D3/I2S1_SDO0_M0  [project net ARED5]
LCDC_D4: U1.25 ; off-sheet LCDC_D4  [project net ARED6]
LCDC_D5: U1.27 ; off-sheet LCDC_D5  [project net ARED7]
LCDC_D6: U1.26 ; off-sheet LCDC_D6  [project net AGRN2]
LCDC_D7/I2S1_SDI0_M0: U1.28 ; off-sheet LCDC_D7/I2S1_SDI0_M0  [project net AGRN3]
LCDC_D8/MAC_CLK: U1.29 ; off-sheet LCDC_D8/MAC_CLK  [project net AGRN4]
LCDC_D9/MAC_MDC: U1.30 ; off-sheet LCDC_D9/MAC_MDC  [project net AGRN5]
LCDC_D10/MAC_MDIO: U1.31 ; off-sheet LCDC_D10/MAC_MDIO  [project net AGRN6]
LCDC_D11/MAC_RXER: U1.32 ; off-sheet LCDC_D11/MAC_RXER  [project net AGRN7]
LCDC_D12/MAC_RXDV: U1.33 ; off-sheet LCDC_D12/MAC_RXDV  [project net ABLU2]
LCDC_D13/MAC_TXEN: U1.35 ; off-sheet LCDC_D13/MAC_TXEN  [project net ABLU4]
LCDC_D14/MAC_TXD0: U1.34 ; off-sheet LCDC_D14/MAC_TXD0  [project net ABLU3]
LCDC_D15/MAC_TXD1: U1.37 ; off-sheet LCDC_D15/MAC_TXD1  [project net ABLU6]
LCDC_D16/MAC_RXD0: U1.36 ; off-sheet LCDC_D16/MAC_RXD0  [project net ABLU5]
LCDC_D17/MAC_RXD1: U1.38 ; off-sheet LCDC_D17/MAC_RXD1  [project net ABLU7]
LCDC_DEN/I2S1_SCLK_TX_M0: U1.20 ; off-sheet LCDC_DEN/I2S1_SCLK_TX_M0  [project net DENA]
LCDC_HSYNC: U1.19 ; off-sheet LCDC_HSYNC  [project net DHS]
LCDC_VSYNC: U1.18 ; off-sheet LCDC_VSYNC  [project net DVS]
LINEOUT_L: J1.29 U1.79 ; off-sheet LINEOUT_L
LINEOUT_R: J1.30 U1.78 ; off-sheet LINEOUT_R
M_DM1: U1.109 ; off-sheet M_DM1
M_DP1: U1.110 ; off-sheet M_DP1
maskrom: U1.43 ; off-sheet maskrom
MICN4: J1.8 U1.83 ; off-sheet MICN4
MICN5: J1.10 U1.85 ; off-sheet MICN5
MICN6: J1.14 U1.87 ; off-sheet MICN6
MICN7: J1.16 U1.89 ; off-sheet MICN7
MICN8: J1.20 U1.91 ; off-sheet MICN8
MICP4: J1.7 U1.84 ; off-sheet MICP4
MICP5: J1.11 U1.86 ; off-sheet MICP5
MICP6: J1.13 U1.88 ; off-sheet MICP6
MICP7: J1.17 U1.90 ; off-sheet MICP7
MICP8: J1.19 U1.92 ; off-sheet MICP8
PHONE_DET: J1.23 U1.82 ; off-sheet PHONE_DET
PWM3/GPIO0_C0/IR_RX: U1.15 ; off-sheet PWM3/GPIO0_C0/IR_RX
RESET: U1.96 ; off-sheet RESET
SPDIF_TX: U1.2 ; off-sheet SPDIF_TX
SPI2_CLK: U1.41 ; off-sheet SPI2_CLK
SPI2_CS: U1.42 ; off-sheet SPI2_CS
SPI2_RX/UART2_RX_M0: U1.39 ; off-sheet SPI2_RX/UART2_RX_M0
SPI2_TX/UART2_TX_M0: U1.40 ; off-sheet SPI2_TX/UART2_TX_M0
TF_CLK: U1.117 ; off-sheet TF_CLK  [project net SDMMC_CLK]
TF_CMD: U1.115 ; off-sheet TF_CMD  [project net SDMMC_CMD]
TF_D0: U1.118 ; off-sheet TF_D0  [project net SDMMC_D0]
TF_D1: U1.119 ; off-sheet TF_D1  [project net SDMMC_D1]
TF_D2: U1.113 ; off-sheet TF_D2  [project net SDMMC_D2/UART2_RX_M1]
TF_D3: U1.114 ; off-sheet TF_D3  [project net SDMMC_D3/UART2_TX_M1]
TF_DET: U1.120 ; off-sheet TF_DET  [project net SDMMC_DET]
UART0_CTS/SPI0_CLK/I2C2_SDA: U1.73 ; off-sheet UART0_CTS/SPI0_CLK/I2C2_SDA  [project net I2C2_SDA]
UART0_RTS/SPI0_CSN/I2C2_SCL: U1.72 ; off-sheet UART0_RTS/SPI0_CSN/I2C2_SCL  [project net I2C2_SCL]
UART0_RX/SPI0_RX: U1.75 ; off-sheet UART0_RX/SPI0_RX
UART0_TX/SPI0_TX: U1.74 ; off-sheet UART0_TX/SPI0_TX
USB_DRV: U1.108 ; off-sheet USB_DRV
USB_ID: R2.2 U1.104 ; off-sheet USB_ID

Not connected (* = marked no-connect by the designer): J1 6 12 18 22 28 31(GND_31) 32(GND_32); TP1 1; TP2 1; TP3 1; TP4 1; U1 95

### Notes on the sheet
- TFCARD

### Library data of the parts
C1 = CAP NP: as C26 on sheet 05
J1 = LCD_Hitachi_TX05D99VM1AAA_1
R1 = RESISTOR: 通用厚膜电阻,51K,+/-1%,R0402,1/16W.; Manufacturer PN: RC0402FR-0751KL; Manufacturer: YAGEO; Wattage: 1/16W; Priority: A
R2 R3 = RESISTOR: as R32 on sheet 05
U1 = 35x35_moudel_0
